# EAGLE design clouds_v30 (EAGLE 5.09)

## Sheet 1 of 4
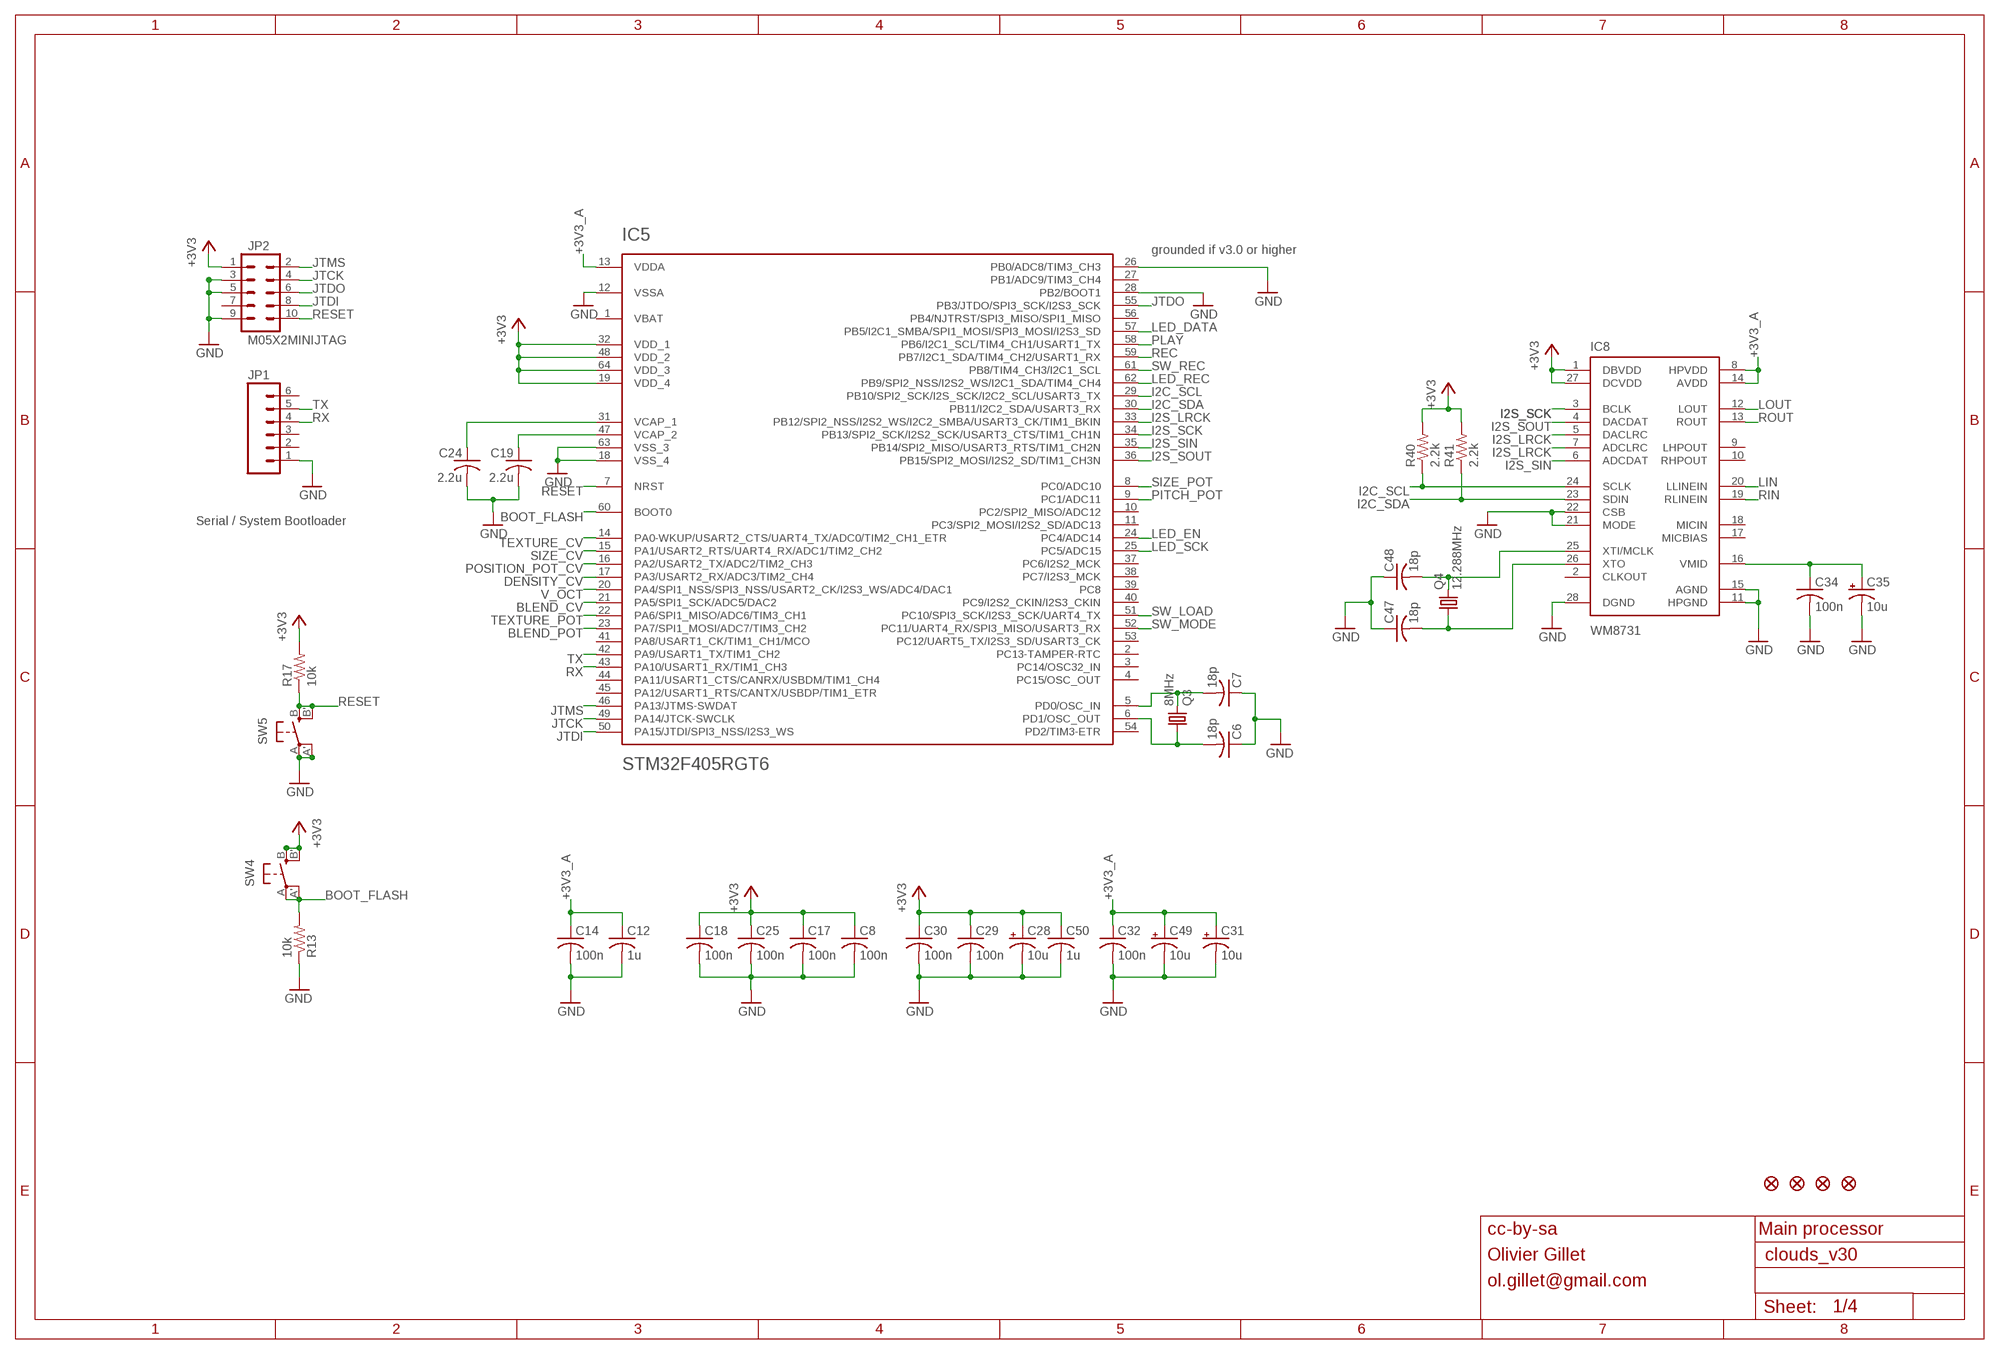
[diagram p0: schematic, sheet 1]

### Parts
C6  18p  C-USC0603  [C0603]
C7  18p  C-USC0603  [C0603]
C8  100n  C-USC0603  [C0603]
C12  1u  C-USC0603  [C0603]
C14  100n  C-USC0603  [C0603]
C17  100n  C-USC0603  [C0603]
C18  100n  C-USC0603  [C0603]
C19  2.2u  C-USC0805  [C0805]
C24  2.2u  C-USC0805  [C0805]
C25  100n  C-USC0603  [C0603]
C28  10u  CPOL-USA  [PANASONIC_A]
C29  100n  C-USC0603  [C0603]
C30  100n  C-USC0603  [C0603]
C31  10u  CPOL-USB  [PANASONIC_B]
C32  100n  C-USC0603  [C0603]
C34  100n  C-USC0603  [C0603]
C35  10u  CPOL-USB  [PANASONIC_B]
C47  18p  C-USC0603  [C0603]
C48  18p  C-USC0603  [C0603]
C49  10u  CPOL-USA  [PANASONIC_A]
C50  1u  C-USC0603  [C0603]
F1  FIDUCIAL1X2  [FIDUCIAL-1X2]
F2  FIDUCIAL1X2  [FIDUCIAL-1X2]
F3  FIDUCIAL1X2  [FIDUCIAL-1X2]
F4  FIDUCIAL1X2  [FIDUCIAL-1X2]
IC5  STM32F405RGT6  STM32F20X  [TQFP-10X10-64]
IC8  WM8731  [SSOP28]
JP1  M06SIP  [1X06]
JP2  M05X2MINIJTAG  [2X5-1.27]
Q3  8MHz  CRYSTALHC49UP  [HC49UP]
Q4  12.288MHz  CRYSTALHC49UP  [HC49UP]
R13  10k  R-US_R0603  [R0603]
R17  10k  R-US_R0603  [R0603]
R40  2.2k  R-US_R0603  [R0603]
R41  2.2k  R-US_R0603  [R0603]
SW4  EVQQ2  [EVQ-Q2]
SW5  EVQQ2  [EVQ-Q2]

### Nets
+3V3: C8.1 C17.1 C18.1 C25.1 C28.+ C29.1 C30.1 C50.1 IC5.19(VDD_4) IC5.32(VDD_1) IC5.48(VDD_2) IC5.64(VDD_3) IC8.1(DBVDD) IC8.27(DCVDD) JP2.1 R17.2 R40.2 R41.2 SW4.B'(S1) SW4.B(S) ; also sheet 3,4
+3V3_A: C12.1 C14.1 C31.+ C32.1 C49.+ IC5.13(VDDA) IC8.8(HPVDD) IC8.14(AVDD) ; also sheet 2,3,4
BLEND_CV: IC5.21(PA5/SPI1_SCK/ADC5/DAC2) ; also sheet 2
BLEND_POT: IC5.23(PA7/SPI1_MOSI/ADC7/TIM3_CH2) ; also sheet 3
BOOT_FLASH: IC5.60(BOOT0) R13.2 SW4.A'(P1) SW4.A(P)
DENSITY_CV: IC5.17(PA3/USART2_RX/ADC3/TIM2_CH4) ; also sheet 2
GND: C6.1 C7.1 C8.2 C12.2 C14.2 C17.2 C18.2 C19.2 C24.2 C25.2 C28.- C29.2 C30.2 C31.- C32.2 C34.2 C35.- C47.1 C48.1 C49.- C50.2 IC5.12(VSSA) IC5.18(VSS_4) IC5.26(PB0/ADC8/TIM3_CH3) IC5.28(PB2/BOOT1) IC5.63(VSS_3) IC8.11(HPGND) IC8.15(AGND) IC8.21(MODE) IC8.22(CSB) IC8.28(DGND) JP1.1 JP2.3 JP2.5 JP2.9 R13.1 SW5.A'(P1) SW5.A(P) ; also sheet 2,3,4
I2C_SCL: IC5.29(PB10/SPI2_SCK/I2S_SCK/I2C2_SCL/USART3_TX) IC8.24(SCLK) R40.1
I2C_SDA: IC5.30(PB11/I2C2_SDA/USART3_RX) IC8.23(SDIN) R41.1
I2S_LRCK: IC5.33(PB12/SPI2_NSS/I2S2_WS/I2C2_SMBA/USART3_CK/TIM1_BKIN) IC8.5(DACLRC) IC8.7(ADCLRC)
I2S_SCK: IC5.34(PB13/SPI2_SCK/I2S2_SCK/USART3_CTS/TIM1_CH1N) IC8.3(BCLK)
I2S_SIN: IC5.35(PB14/SPI2_MISO/USART3_RTS/TIM1_CH2N) IC8.6(ADCDAT)
I2S_SOUT: IC5.36(PB15/SPI2_MOSI/I2S2_SD/TIM1_CH3N) IC8.4(DACDAT)
JTCK: IC5.49(PA14/JTCK-SWCLK) JP2.4
JTDI: IC5.50(PA15/JTDI/SPI3_NSS/I2S3_WS) JP2.8
JTDO: IC5.55(PB3/JTDO/SPI3_SCK/I2S3_SCK) JP2.6
JTMS: IC5.46(PA13/JTMS-SWDAT) JP2.2
LED_DATA: IC5.57(PB5/I2C1_SMBA/SPI1_MOSI/SPI3_MOSI/I2S3_SD) ; also sheet 3
LED_EN: IC5.24(PC4/ADC14) ; also sheet 3
LED_REC: IC5.62(PB9/SPI2_NSS/I2S2_WS/I2C1_SDA/TIM4_CH4) ; also sheet 3
LED_SCK: IC5.25(PC5/ADC15) ; also sheet 3
LIN: IC8.20(LLINEIN) ; also sheet 2
LOUT: IC8.12(LOUT) ; also sheet 2
N$7: C7.2 IC5.5(PD0/OSC_IN) Q3.2
N$8: C6.2 IC5.6(PD1/OSC_OUT) Q3.1
N$13: C19.1 IC5.47(VCAP_2)
N$17: C34.1 C35.+ IC8.16(VMID)
N$19: C24.1 IC5.31(VCAP_1)
N$59: C47.2 IC8.26(XTO) Q4.1
N$60: C48.2 IC8.25(XTI/MCLK) Q4.2
PITCH_POT: IC5.9(PC1/ADC11) ; also sheet 3
PLAY: IC5.58(PB6/I2C1_SCL/TIM4_CH1/USART1_TX) ; also sheet 3
POSITION_POT_CV: IC5.16(PA2/USART2_TX/ADC2/TIM2_CH3) ; also sheet 2
REC: IC5.59(PB7/I2C1_SDA/TIM4_CH2/USART1_RX) ; also sheet 3
RESET: IC5.7(NRST) JP2.10 R17.1 SW5.B'(S1) SW5.B(S)
RIN: IC8.19(RLINEIN) ; also sheet 2
ROUT: IC8.13(ROUT) ; also sheet 2
RX: IC5.43(PA10/USART1_RX/TIM1_CH3) JP1.4
SIZE_CV: IC5.15(PA1/USART2_RTS/UART4_RX/ADC1/TIM2_CH2) ; also sheet 2
SIZE_POT: IC5.8(PC0/ADC10) ; also sheet 3
SW_LOAD: IC5.51(PC10/SPI3_SCK/I2S3_SCK/UART4_TX) ; also sheet 3
SW_MODE: IC5.52(PC11/UART4_RX/SPI3_MISO/USART3_RX) ; also sheet 3
SW_REC: IC5.61(PB8/TIM4_CH3/I2C1_SCL) ; also sheet 3
TEXTURE_CV: IC5.14(PA0-WKUP/USART2_CTS/UART4_TX/ADC0/TIM2_CH1_ETR) ; also sheet 2
TEXTURE_POT: IC5.22(PA6/SPI1_MISO/ADC6/TIM3_CH1) ; also sheet 3
TX: IC5.42(PA9/USART1_TX/TIM1_CH2) JP1.5
V_OCT: IC5.20(PA4/SPI1_NSS/SPI3_NSS/USART2_CK/I2S3_WS/ADC4/DAC1) ; also sheet 2
Unconnected: IC5.2(PC13-TAMPER-RTC) IC5.3(PC14/OSC32_IN) IC5.4(PC15/OSC_OUT) IC5.10(PC2/SPI2_MISO/ADC12) IC5.11(PC3/SPI2_MOSI/I2S2_SD/ADC13) IC5.27(PB1/ADC9/TIM3_CH4) IC5.37(PC6/I2S2_MCK) IC5.38(PC7/I2S3_MCK) IC5.39(PC8) IC5.40(PC9/I2S2_CKIN/I2S3_CKIN) IC5.41(PA8/USART1_CK/TIM1_CH1/MCO) IC5.44(PA11/USART1_CTS/CANRX/USBDM/TIM1_CH4) IC5.45(PA12/USART1_RTS/CANTX/USBDP/TIM1_ETR) IC5.53(PC12/UART5_TX/I2S3_SD/USART3_CK) IC5.54(PD2/TIM3-ETR) IC5.56(PB4/NJTRST/SPI3_MISO/SPI1_MISO) IC8.2(CLKOUT) IC8.9(LHPOUT) IC8.10(RHPOUT) IC8.17(MICBIAS) IC8.18(MICIN) JP1.2 JP1.3 JP1.6 JP2.7

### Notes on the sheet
- grounded if v3.0 or higher
- Serial / System Bootloader
- cc-by-sa | Main processor
- Olivier Gillet
- ol.gillet@gmail.com

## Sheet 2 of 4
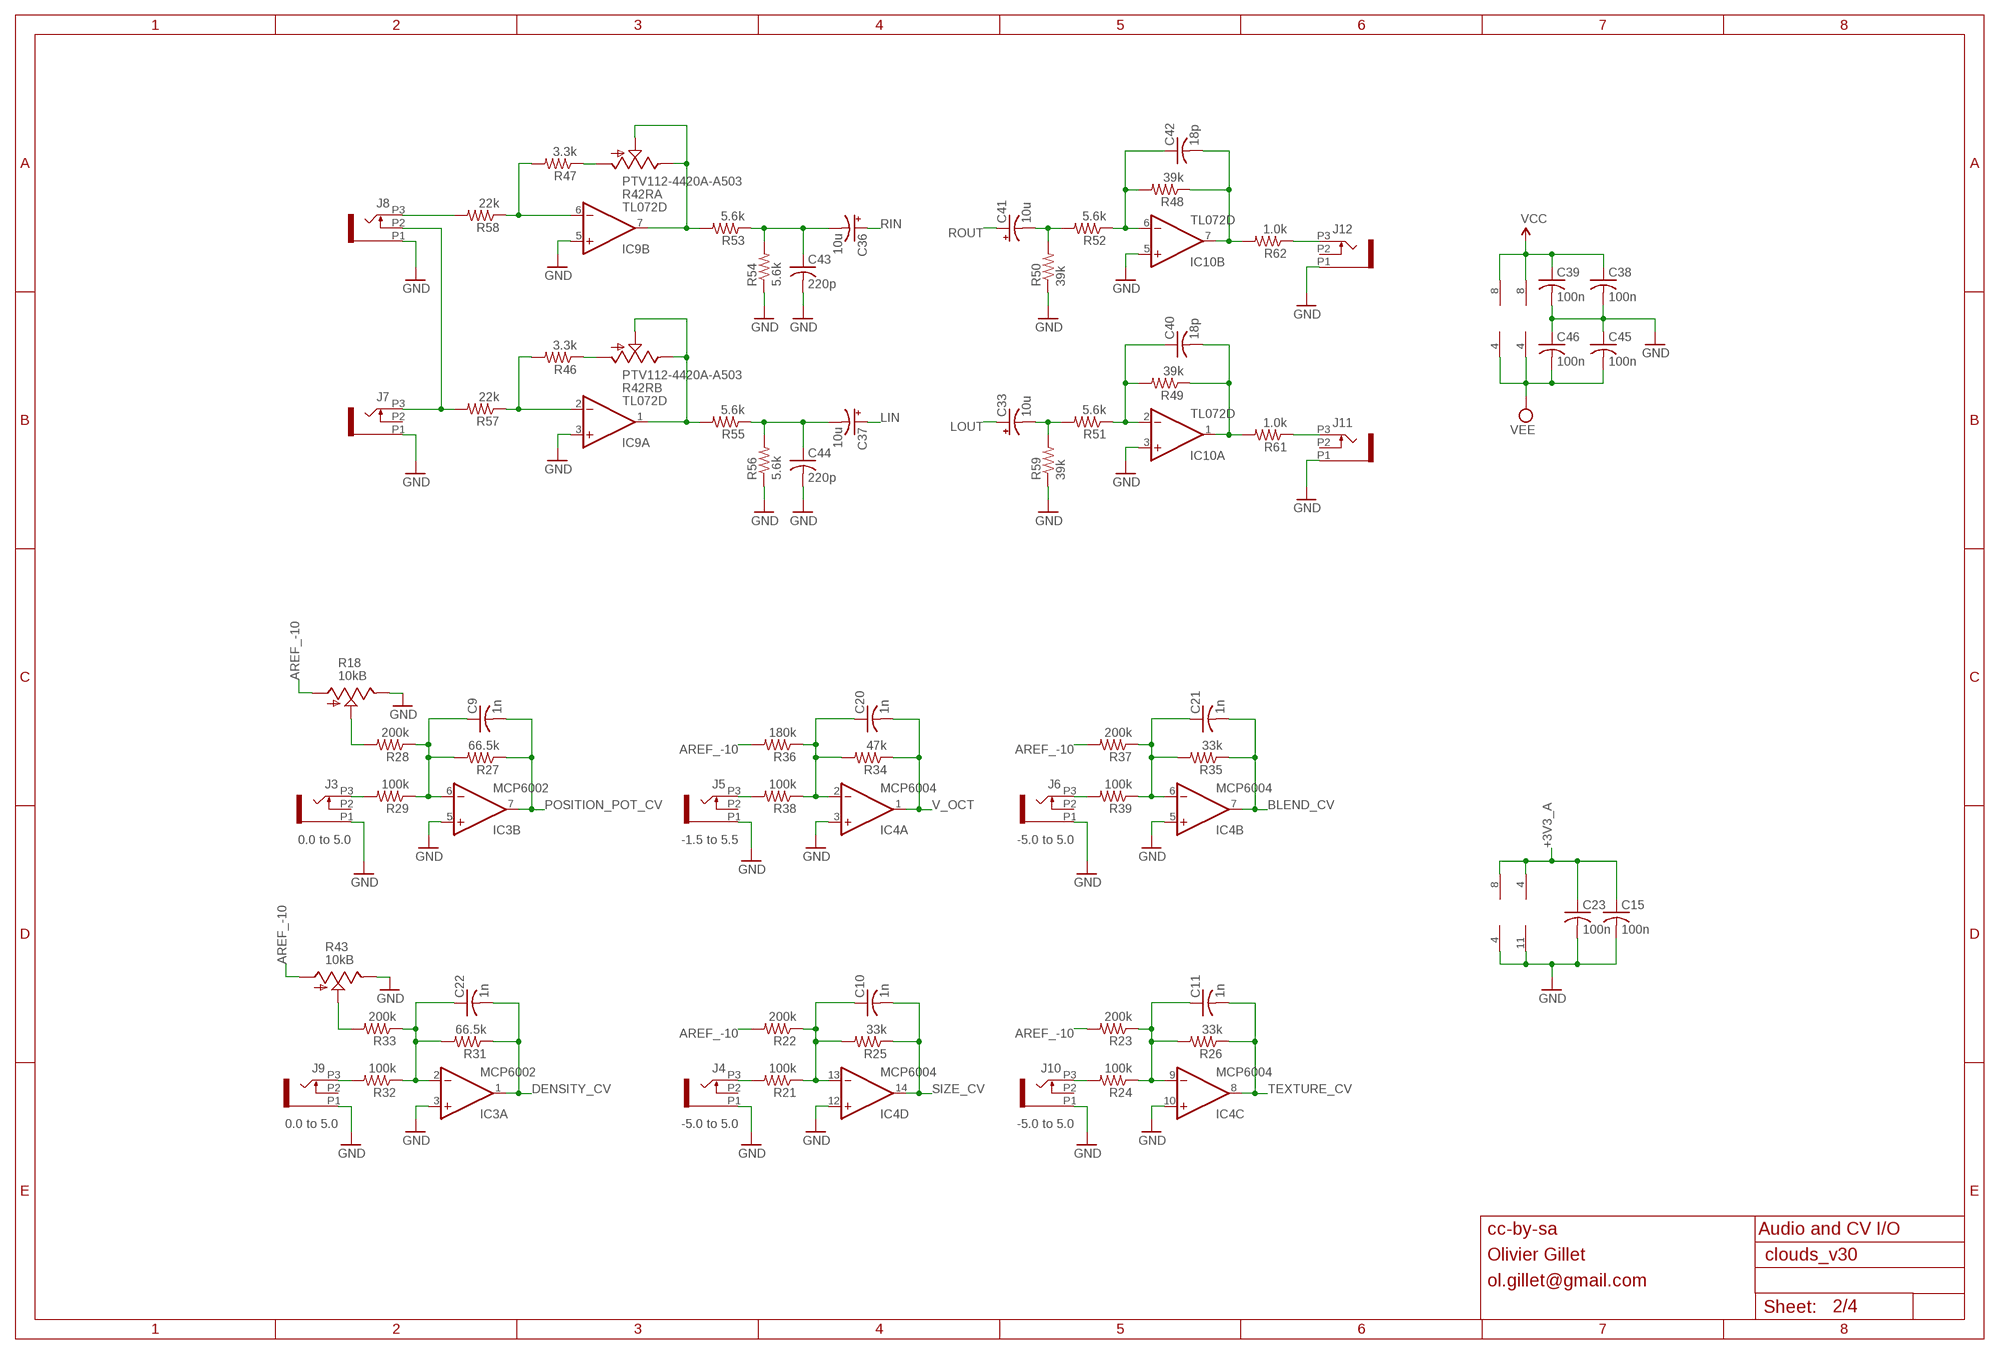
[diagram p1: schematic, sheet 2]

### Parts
C9  1n  C-USC0603  [C0603]
C10  1n  C-USC0603  [C0603]
C11  1n  C-USC0603  [C0603]
C15  100n  C-USC0603  [C0603]
C20  1n  C-USC0603  [C0603]
C21  1n  C-USC0603  [C0603]
C22  1n  C-USC0603  [C0603]
C23  100n  C-USC0603  [C0603]
C33  10u  CPOL-USB  [PANASONIC_B]
C36  10u  CPOL-USB  [PANASONIC_B]
C37  10u  CPOL-USB  [PANASONIC_B]
C38  100n  C-USC0603  [C0603]
C39  100n  C-USC0603  [C0603]
C40  18p  C-USC0603  [C0603]
C41  10u  CPOL-USB  [PANASONIC_B]
C42  18p  C-USC0603  [C0603]
C43  220p  C-USC0603  [C0603]
C44  220p  C-USC0603  [C0603]
C45  100n  C-USC0603  [C0603]
C46  100n  C-USC0603  [C0603]
IC3  MCP6002  TL072D  [SO08]
IC4  MCP6004  TL074D  [SO14]
IC9  TL072D  [SO08]
IC10  TL072D  [SO08]
J3  PJ301_THONKICONN6  [WQP_PJ_301M6]
J4  PJ301_THONKICONN6  [WQP_PJ_301M6]
J5  PJ301_THONKICONN6  [WQP_PJ_301M6]
J6  PJ301_THONKICONN6  [WQP_PJ_301M6]
J7  PJ301_THONKICONN6  [WQP_PJ_301M6]
J8  PJ301_THONKICONN6  [WQP_PJ_301M6]
J9  PJ301_THONKICONN6  [WQP_PJ_301M6]
J10  PJ301_THONKICONN6  [WQP_PJ_301M6]
J11  PJ301_THONKICONN6  [WQP_PJ_301M6]
J12  PJ301_THONKICONN6  [WQP_PJ_301M6]
R18  10kB  POT_USVERTICAL_PS  [ALPS_POT_VERTICAL_PS]
R21  100k  R-US_R0603  [R0603]
R22  200k  R-US_R0603  [R0603]
R23  200k  R-US_R0603  [R0603]
R24  100k  R-US_R0603  [R0603]
R25  33k  R-US_R0603  [R0603]
R26  33k  R-US_R0603  [R0603]
R27  66.5k  R-US_R0603  [R0603]
R28  200k  R-US_R0603  [R0603]
R29  100k  R-US_R0603  [R0603]
R31  66.5k  R-US_R0603  [R0603]
R32  100k  R-US_R0603  [R0603]
R33  200k  R-US_R0603  [R0603]
R34  47k  R-US_R0603  [R0603]
R35  33k  R-US_R0603  [R0603]
R36  180k  R-US_R0603  [R0603]
R37  200k  R-US_R0603  [R0603]
R38  100k  R-US_R0603  [R0603]
R39  100k  R-US_R0603  [R0603]
R42  PTV112-4420A-A503  POT_US_DUAL_GANG  [BOURNS_PTV112]
R43  10kB  POT_USVERTICAL_PS  [ALPS_POT_VERTICAL_PS]
R46  3.3k  R-US_R0603  [R0603]
R47  3.3k  R-US_R0603  [R0603]
R48  39k  R-US_R0603  [R0603]
R49  39k  R-US_R0603  [R0603]
R50  39k  R-US_R0603  [R0603]
R51  5.6k  R-US_R0603  [R0603]
R52  5.6k  R-US_R0603  [R0603]
R53  5.6k  R-US_R0603  [R0603]
R54  5.6k  R-US_R0603  [R0603]
R55  5.6k  R-US_R0603  [R0603]
R56  5.6k  R-US_R0603  [R0603]
R57  22k  R-US_R0603  [R0603]
R58  22k  R-US_R0603  [R0603]
R59  39k  R-US_R0603  [R0603]
R61  1.0k  R-US_R0603  [R0603]
R62  1.0k  R-US_R0603  [R0603]

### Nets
+3V3_A: C15.1 C23.1 IC3.8(P:V+) IC4.4(P:V+) ; also sheet 1,3,4
AREF_-10: R18.P$3(A) R22.2 R23.2 R36.2 R37.2 R43.P$3(A) ; also sheet 4
BLEND_CV: C21.2 IC4.7(B:OUT) R35.1 ; also sheet 1
DENSITY_CV: C22.2 IC3.1(A:OUT) R31.1 ; also sheet 1
GND: C15.2 C23.2 C38.2 C39.2 C43.2 C44.2 C45.1 C46.1 IC3.3(A:+IN) IC3.4(P:V-) IC3.5(B:+IN) IC4.3(A:+IN) IC4.5(B:+IN) IC4.10(C:+IN) IC4.11(P:V-) IC4.12(D:+IN) IC9.3(A:+IN) IC9.5(B:+IN) IC10.3(A:+IN) IC10.5(B:+IN) J3.P1 J4.P1 J5.P1 J6.P1 J7.P1 J8.P1 J9.P1 J10.P1 J11.P1 J12.P1 R18.P$1(E) R43.P$1(E) R50.1 R54.1 R56.1 R59.1 ; also sheet 1,3,4
LIN: C37.+ ; also sheet 1
LOUT: C33.+ ; also sheet 1
LOUT_JACK: J11.P3 R61.1
N$1: J4.P3 R21.2
N$2: C10.1 IC4.13(D:-IN) R21.1 R22.1 R25.2
N$4: J10.P3 R24.2
N$5: C11.1 IC4.9(C:-IN) R23.1 R24.1 R26.2
N$6: J6.P3 R39.2
N$10: J5.P3 R38.2
N$11: C20.1 IC4.2(A:-IN) R34.2 R36.1 R38.1
N$14: J9.P3 R32.2
N$15: C21.1 IC4.6(B:-IN) R35.2 R37.1 R39.1
N$18: C37.- C44.1 R55.1 R56.2
N$20: J8.P3 R58.2
N$21: J7.P3 J8.P2 R57.2
N$22: C36.- C43.1 R53.1 R54.2
N$23: C41.- R50.2 R52.2
N$24: C22.1 IC3.2(A:-IN) R31.2 R32.1 R33.1
N$25: C42.1 IC10.6(B:-IN) R48.2 R52.1
N$26: R33.2 R43.P$2(S)
N$27: J3.P3 R29.2
N$28: C42.2 IC10.7(B:OUT) R48.1 R62.2
N$30: C9.1 IC3.6(B:-IN) R27.2 R28.1 R29.1
N$31: C33.- R51.2 R59.2
N$32: C40.1 IC10.2(A:-IN) R49.2 R51.1
N$33: C40.2 IC10.1(A:OUT) R49.1 R61.2
N$35: R18.P$2(S) R28.2
N$42: IC9.7(B:OUT) R42.2P(RA:S) R42.3P(RA:E) R53.2
N$51: IC9.1(A:OUT) R42.2(RB:S) R42.3(RB:E) R55.2
N$52: R42.1P(RA:A) R47.1
N$53: R42.1(RB:A) R46.1
N$54: IC9.6(B:-IN) R47.2 R58.1
N$58: IC9.2(A:-IN) R46.2 R57.1
POSITION_POT_CV: C9.2 IC3.7(B:OUT) R27.1 ; also sheet 1
RIN: C36.+ ; also sheet 1
ROUT: C41.+ ; also sheet 1
ROUT_JACK: J12.P3 R62.1
SIZE_CV: C10.2 IC4.14(D:OUT) R25.1 ; also sheet 1
TEXTURE_CV: C11.2 IC4.8(C:OUT) R26.1 ; also sheet 1
V_OCT: C20.2 IC4.1(A:OUT) R34.1 ; also sheet 1
VCC: C38.1 C39.1 IC9.8(P:V+) IC10.8(P:V+) ; also sheet 4
VEE: C45.2 C46.2 IC9.4(P:V-) IC10.4(P:V-) ; also sheet 4
Unconnected: J3.P2 J4.P2 J5.P2 J6.P2 J7.P2 J9.P2 J10.P2 J11.P2 J12.P2

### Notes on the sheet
- 0.0 to 5.0 | -1.5 to 5.5 | -5.0 to 5.0
- 0.0 to 5.0 | -5.0 to 5.0 | -5.0 to 5.0
- cc-by-sa | Audio and CV I/O
- Olivier Gillet
- ol.gillet@gmail.com

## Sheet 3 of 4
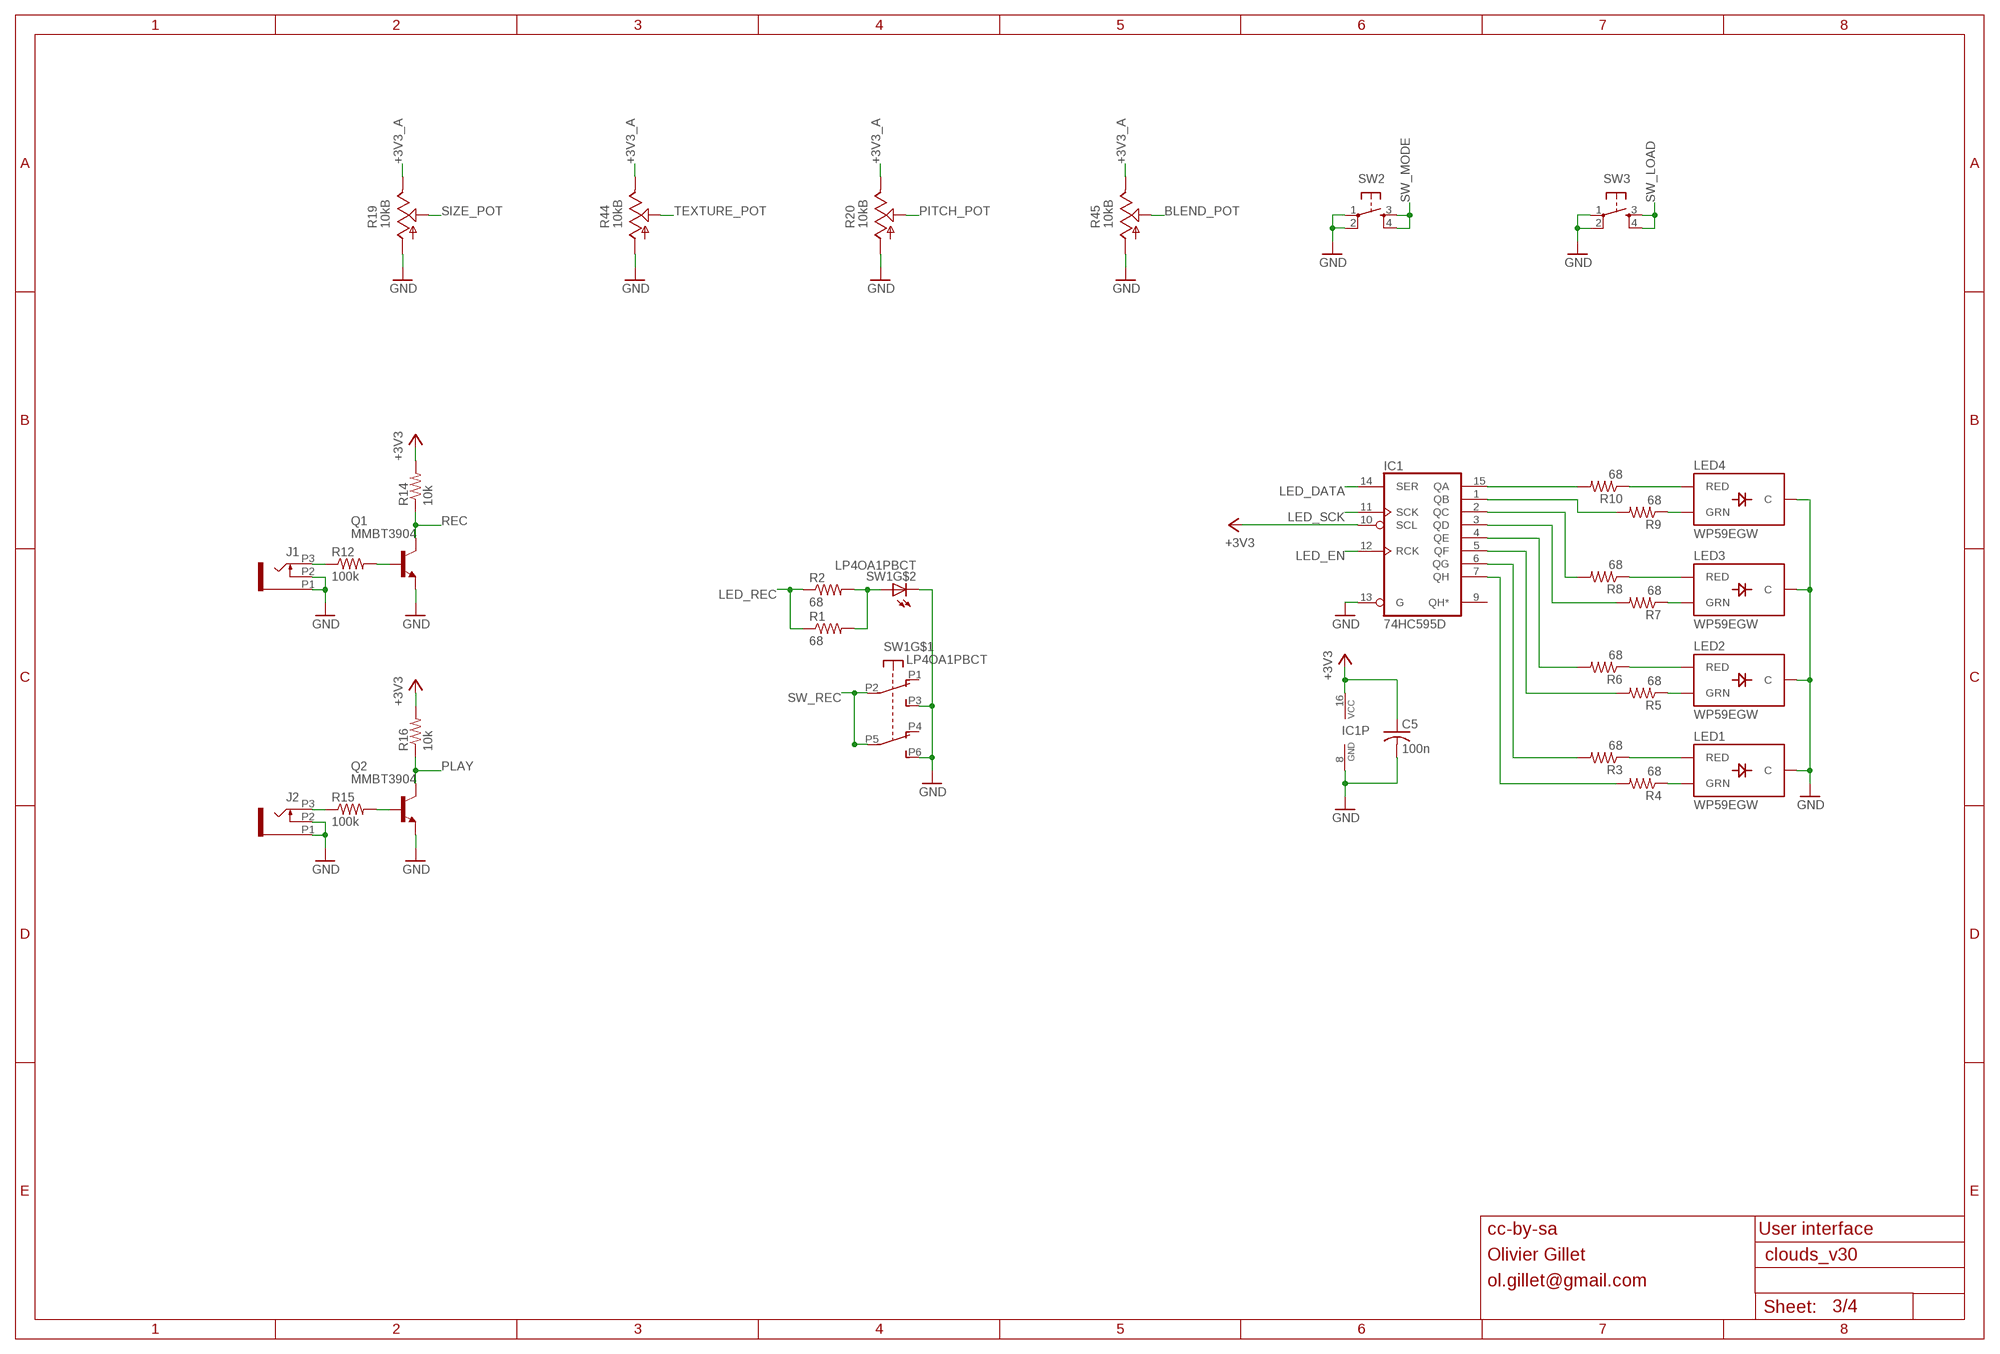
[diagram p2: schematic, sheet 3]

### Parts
C5  100n  C-USC0603  [C0603]
IC1  74HC595D  [SO16]
J1  PJ301_THONKICONN6  [WQP_PJ_301M6]
J2  PJ301_THONKICONN6  [WQP_PJ_301M6]
LED1  WP59EGW  LED-BICOLOR-THROUGHHOLE5MM  [LED-BICOLOR-THROUGHHOLE-5MM]
LED2  WP59EGW  LED-BICOLOR-THROUGHHOLE5MM  [LED-BICOLOR-THROUGHHOLE-5MM]
LED3  WP59EGW  LED-BICOLOR-THROUGHHOLE5MM  [LED-BICOLOR-THROUGHHOLE-5MM]
LED4  WP59EGW  LED-BICOLOR-THROUGHHOLE5MM  [LED-BICOLOR-THROUGHHOLE-5MM]
Q1  MMBT3904  MMBT3904LT1-NPN-SOT23-BEC  [SOT23-BEC]
Q2  MMBT3904  MMBT3904LT1-NPN-SOT23-BEC  [SOT23-BEC]
R1  68  R-US_R0603  [R0603]
R2  68  R-US_R0603  [R0603]
R3  68  R-US_R0603  [R0603]
R4  68  R-US_R0603  [R0603]
R5  68  R-US_R0603  [R0603]
R6  68  R-US_R0603  [R0603]
R7  68  R-US_R0603  [R0603]
R8  68  R-US_R0603  [R0603]
R9  68  R-US_R0603  [R0603]
R10  68  R-US_R0603  [R0603]
R12  100k  R-US_R0603  [R0603]
R14  10k  R-US_R0603  [R0603]
R15  100k  R-US_R0603  [R0603]
R16  10k  R-US_R0603  [R0603]
R19  10kB  POT_USVERTICAL_PS  [ALPS_POT_VERTICAL_PS]
R20  10kB  POT_USVERTICAL_PS  [ALPS_POT_VERTICAL_PS]
R44  10kB  POT_USVERTICAL_PS  [ALPS_POT_VERTICAL_PS]
R45  10kB  POT_USVERTICAL_PS  [ALPS_POT_VERTICAL_PS]
SW1  LP4OA1PBCT  [LP4OA1PBCT]
SW2  TAC_SWITCHPTH  [TACTILE-PTH]
SW3  TAC_SWITCHPTH  [TACTILE-PTH]

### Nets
+3V3: C5.1 IC1.10(SCL) IC1.16(VCC) R14.2 R16.2 ; also sheet 1,4
+3V3_A: R19.P$1(E) R20.P$1(E) R44.P$1(E) R45.P$1(E) ; also sheet 1,2,4
BLEND_POT: R45.P$2(S) ; also sheet 1
GND: C5.2 IC1.8(GND) IC1.13(G) J1.P1 J1.P2 J2.P1 J2.P2 LED1.2(C) LED2.2(C) LED3.2(C) LED4.2(C) Q1.E Q2.E R19.P$3(A) R20.P$3(A) R44.P$3(A) R45.P$3(A) SW1.L2 SW1.P3(A3) SW1.P6(B3) SW2.1 SW2.2 SW3.1 SW3.2 ; also sheet 1,2,4
LED_DATA: IC1.14(SER) ; also sheet 1
LED_EN: IC1.12(RCK) ; also sheet 1
LED_REC: R1.1 R2.1 ; also sheet 1
LED_SCK: IC1.11(SCK) ; also sheet 1
N$9: LED4.3(GRN) R9.1
N$12: LED4.1(RED) R10.1
N$16: LED3.1(RED) R8.1
N$29: LED3.3(GRN) R7.1
N$34: LED2.1(RED) R6.1
N$36: J2.P3 R15.1
N$37: Q2.B R15.2
N$38: R1.2 R2.2 SW1.L1
N$39: LED2.3(GRN) R5.1
N$40: LED1.1(RED) R3.1
N$41: LED1.3(GRN) R4.1
N$43: IC1.15(QA) R10.2
N$44: IC1.1(QB) R9.2
N$45: IC1.2(QC) R8.2
N$46: IC1.3(QD) R7.2
N$47: IC1.4(QE) R6.2
N$48: IC1.5(QF) R5.2
N$49: IC1.6(QG) R3.2
N$50: IC1.7(QH) R4.2
N$57: J1.P3 R12.1
N$66: Q1.B R12.2
PITCH_POT: R20.P$2(S) ; also sheet 1
PLAY: Q2.C R16.1 ; also sheet 1
REC: Q1.C R14.1 ; also sheet 1
SIZE_POT: R19.P$2(S) ; also sheet 1
SW_LOAD: SW3.3 SW3.4 ; also sheet 1
SW_MODE: SW2.3 SW2.4 ; also sheet 1
SW_REC: SW1.P2(A2) SW1.P5(B2) ; also sheet 1
TEXTURE_POT: R44.P$2(S) ; also sheet 1
Unconnected: IC1.9(QH*) SW1.P1(A1) SW1.P4(B1)

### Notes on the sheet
- cc-by-sa | User interface
- Olivier Gillet
- ol.gillet@gmail.com

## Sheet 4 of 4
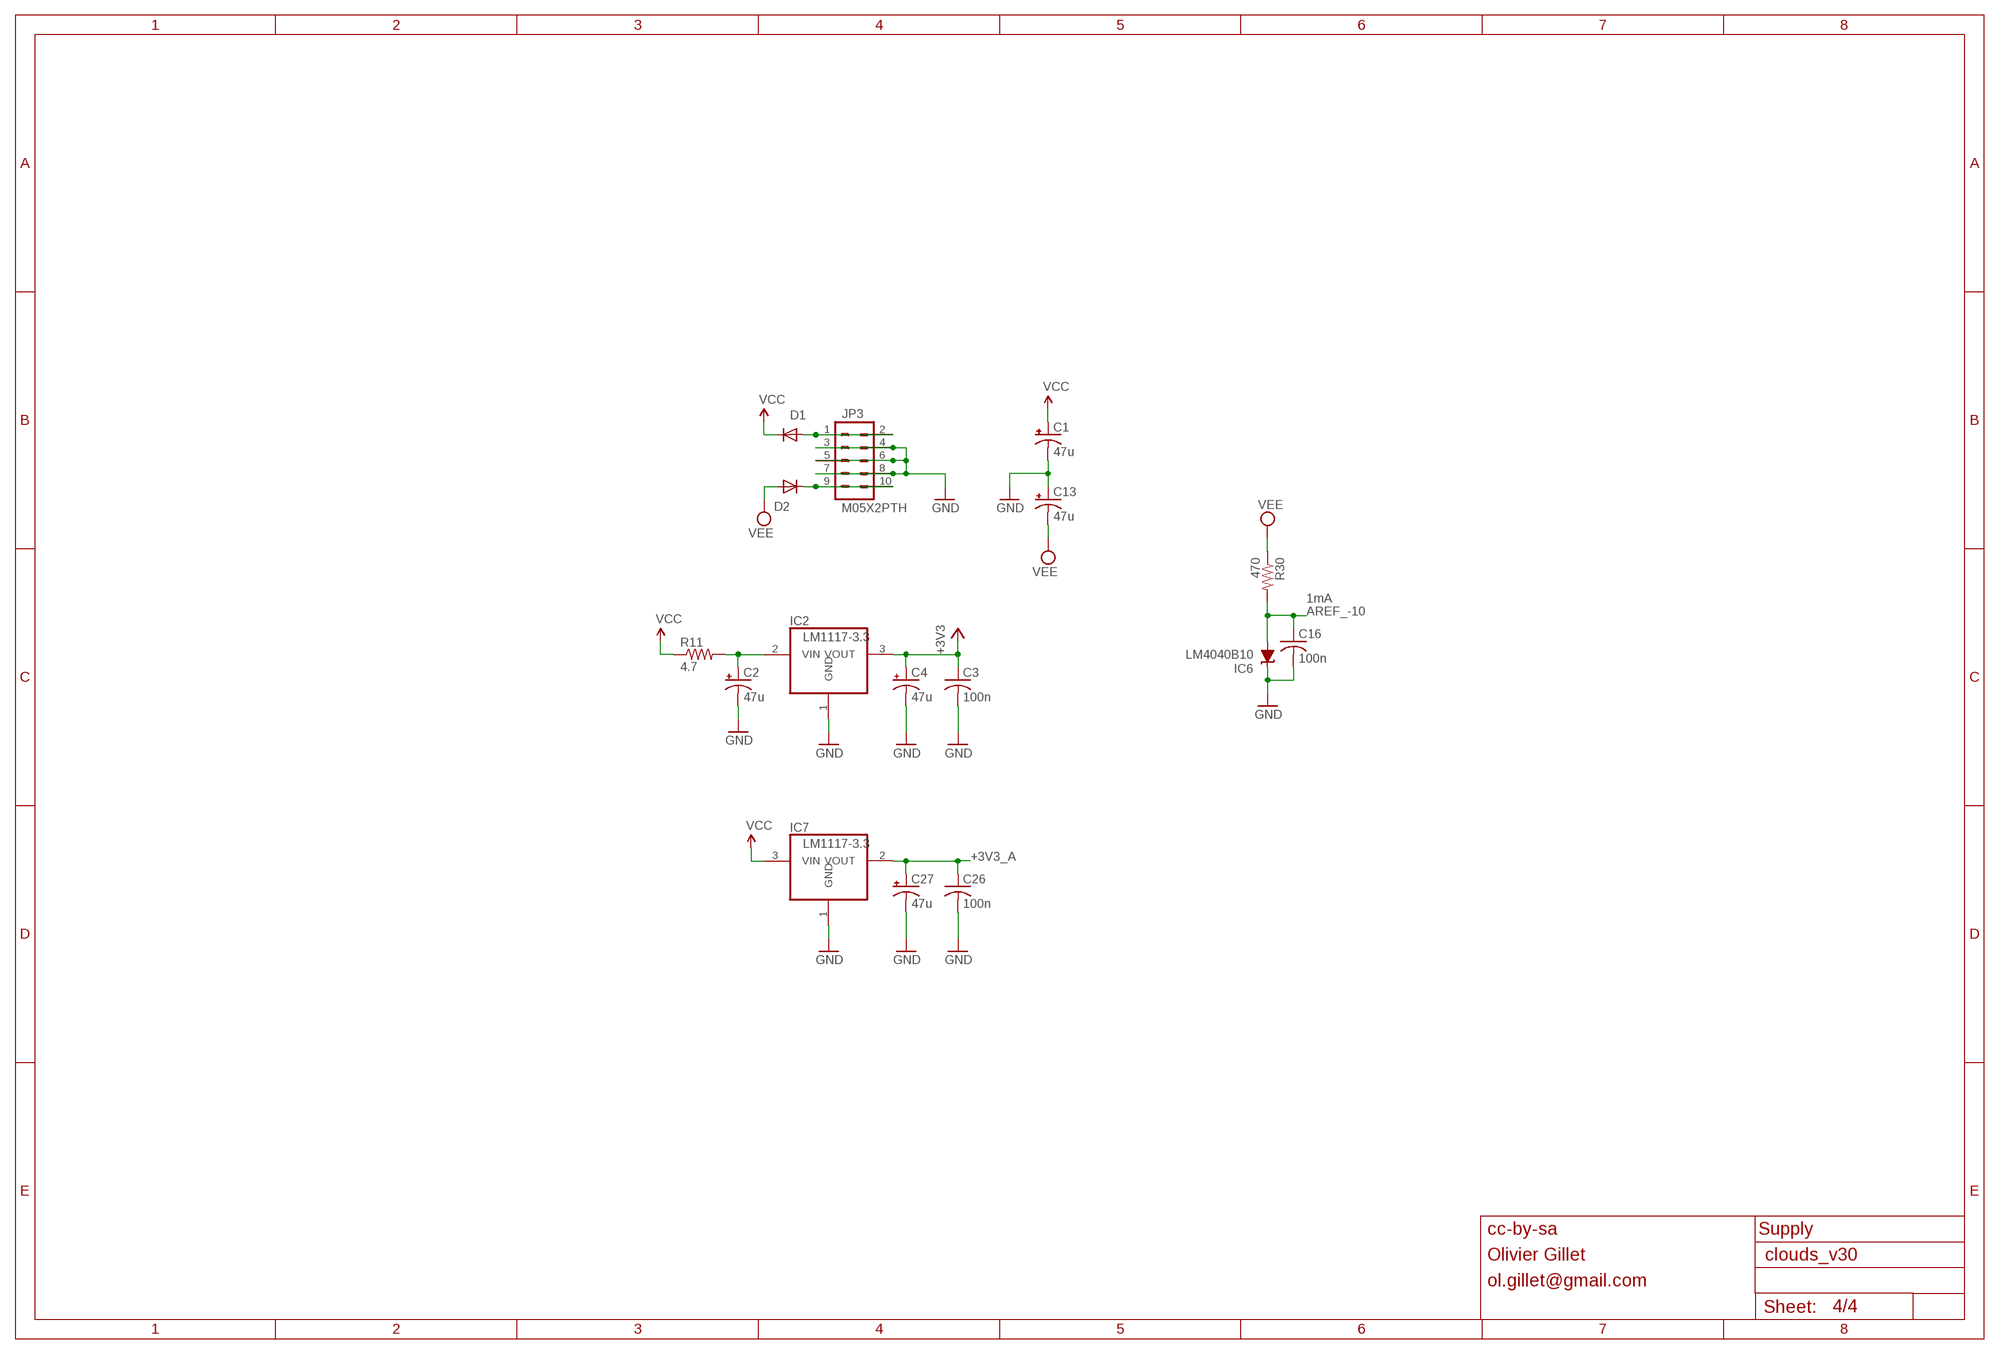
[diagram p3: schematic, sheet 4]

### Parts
C1  47u  CPOL-USD  [PANASONIC_D]
C2  47u  CPOL-USD  [PANASONIC_D]
C3  100n  C-USC0603  [C0603]
C4  47u  CPOL-USD  [PANASONIC_D]
C13  47u  CPOL-USD  [PANASONIC_D]
C16  100n  C-USC0603  [C0603]
C26  100n  C-USC0603  [C0603]
C27  47u  CPOL-USD  [PANASONIC_D]
D1  1N5819HW  DIODE-SOD123  [SOD123]
D2  1N5819HW  DIODE-SOD123  [SOD123]
IC2  LM1117-3.3  REG1117T  [TO252]
IC6  LM4040B10  LM4041B12DBZ  [DBZ_R-PDSO-G3]
IC7  LM1117-3.3  REG1117  [SOT223]
JP3  M05X2PTH  [AVR_ICSP]
R11  4.7  R-US_R1206  [R1206]
R30  470  R-US_R0603  [R0603]

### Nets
+3V3: C3.1 C4.+ IC2.3(VOUT) ; also sheet 1,3
+3V3_A: C26.1 C27.+ IC7.2(VOUT) ; also sheet 1,2,3
AREF_-10: C16.1 IC6.2(A) R30.2 ; also sheet 2
GND: C1.- C2.- C3.2 C4.- C13.+ C16.2 C26.2 C27.- IC2.1(GND) IC6.1(C) IC7.1(GND) JP3.3 JP3.4 JP3.5 JP3.6 JP3.7 JP3.8 ; also sheet 1,2,3
N$55: C2.+ IC2.2(VIN) R11.2
N$56: D1.A JP3.1 JP3.2
N$64: D2.C JP3.9 JP3.10
VCC: C1.+ D1.C IC7.3(VIN) R11.1 ; also sheet 2
VEE: C13.- D2.A R30.1 ; also sheet 2

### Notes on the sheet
- 1mA
- cc-by-sa | Supply
- Olivier Gillet
- ol.gillet@gmail.com

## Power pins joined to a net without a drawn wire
VBAT: IC5.1(VBAT)

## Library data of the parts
C1 C2 C4 C13 C27 C28 C31 C33 C35-C37 C41 C49 = rcl:CPOL-US: POLARIZED CAPACITOR, American symbol
C3 C5-C12 C14-C26 C29 C30 C32 C34 C38-C40 C42-C48 C50 = rcl:C-US: CAPACITOR, American symbol
D1 D2 = diode:DIODE-: DIODE
F1-F4 = SparkFun:FIDUCIAL: Fiducial Alignment Points
IC1 = 74xx-eu:74*595: 8-bit SHIFT REGISTER, output latch
IC2 IC7 = og-vreg:REG1117: 800mA and 1A Low Dropout (LDO) Positive Regulator 1.8V, 2.5V, 2.85V, 3.3V, 5V, and Adj
IC3 = gm-ics:TL072: OP AMP
IC4 = gm-ics:TL074: OP AMP
IC5 = og-stm32f2:STM32F20X
IC6 = texas:LM4041: PRECISION MICROPOWER SHUNT VOLTAGE REFERENCE
IC8 = og-dac:WM8731
IC9 IC10 = og-linear:TL072: OP AMP
J1-J12 = og-pj301:PJ301_THONKICONN
JP1 = SparkFun:M06: Header 6 Standard 6-pin 0.1" header. Use with straight break away headers (SKU : PRT-00116), right angle break away headers (PRT-00553), swiss pins (PRT-00743), machine pins (PRT-00117), and female headers (PRT-00115). Molex polarized connector foot print use with SKU : PRT-08094 with associated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
JP2 JP3 = og-header:M05X2: Header 5x2 Standard 10-pin dual row 0.1" header. Commonly used with AVR-ISP. Use with Spark Fun Electronics SKU: PRT-00778
LED1-LED4 = og-leds:LED-BICOLOR-THROUGHHOLE
Q1 Q2 = transistor:*-NPN-: NPN Transistror BF959 corrected 2008.03.06
Q3 Q4 = crystal:CRYSTAL: CRYSTAL
R1-R17 R21-R41 R46-R59 R61 R62 = rcl:R-US_: RESISTOR, American symbol
R18-R20 R43-R45 = og-pots:POT_US
R42 = og-pots:POT_US_DUAL_GANG
SW1 = og-switch:LP4OA1PBCT
SW2 SW3 = SparkFun:TAC_SWITCH: Momentary Switch Button commonly used for reset or general input. Spark Fun Electronics SKU : COM-00097
SW4 SW5 = adafruit:EVQQ2: SMT 6mm switch, EVQQ2 series http://www.ladyada.net/library/eagle

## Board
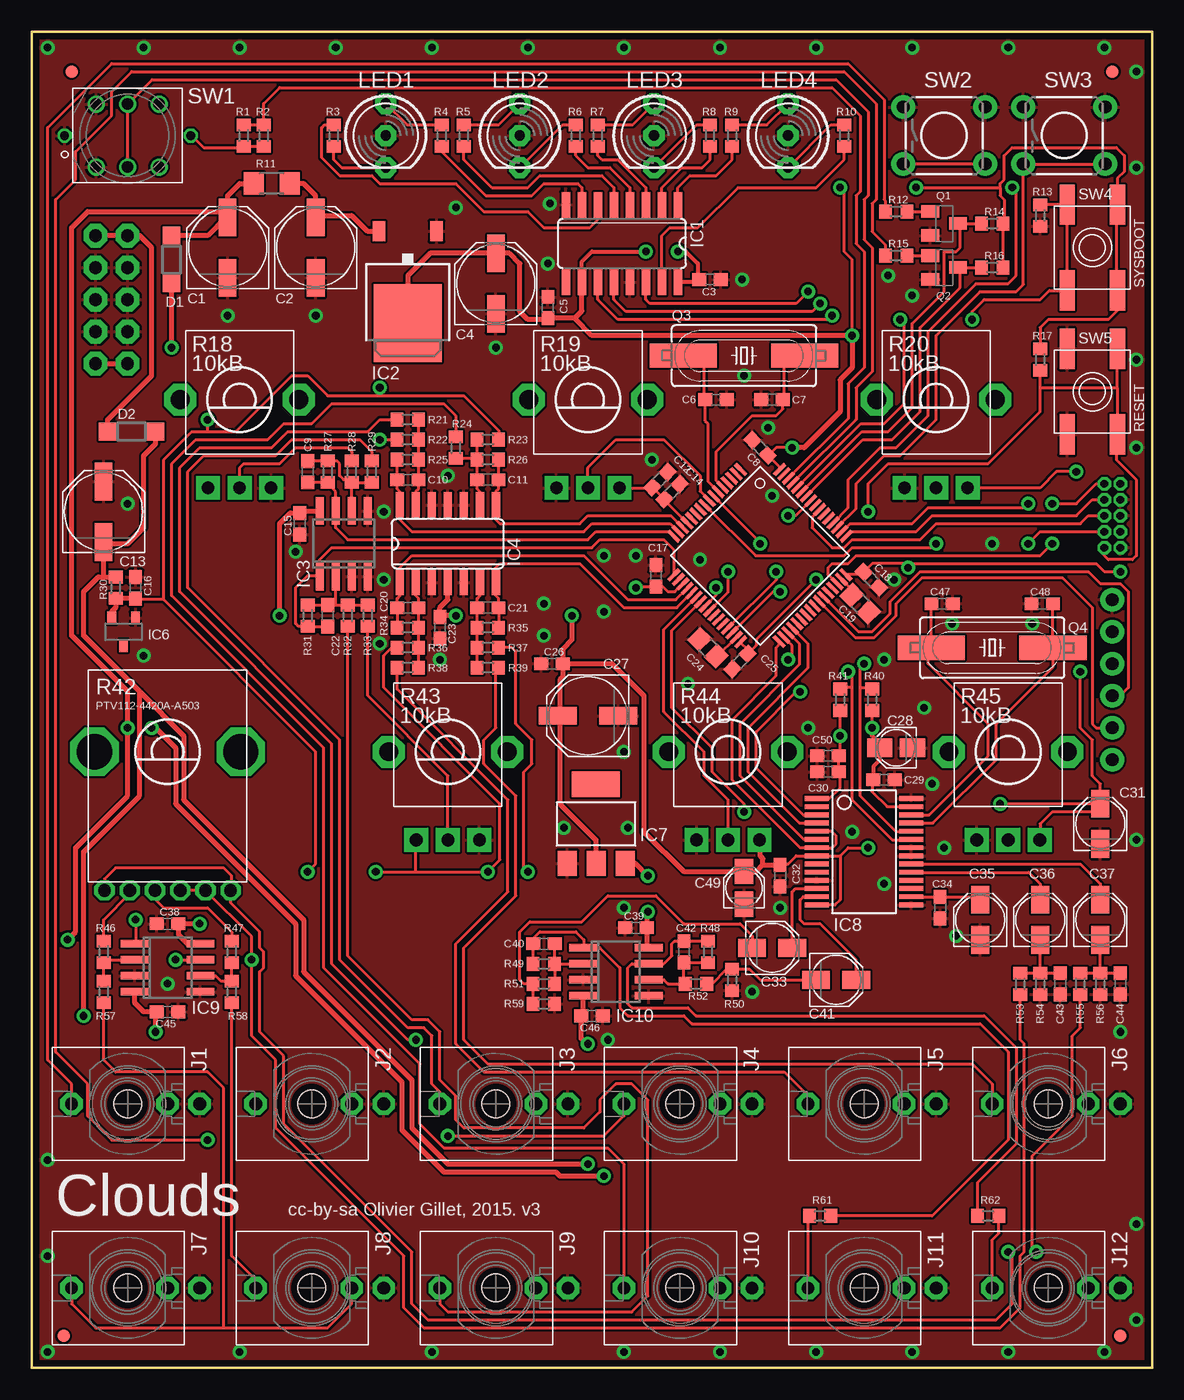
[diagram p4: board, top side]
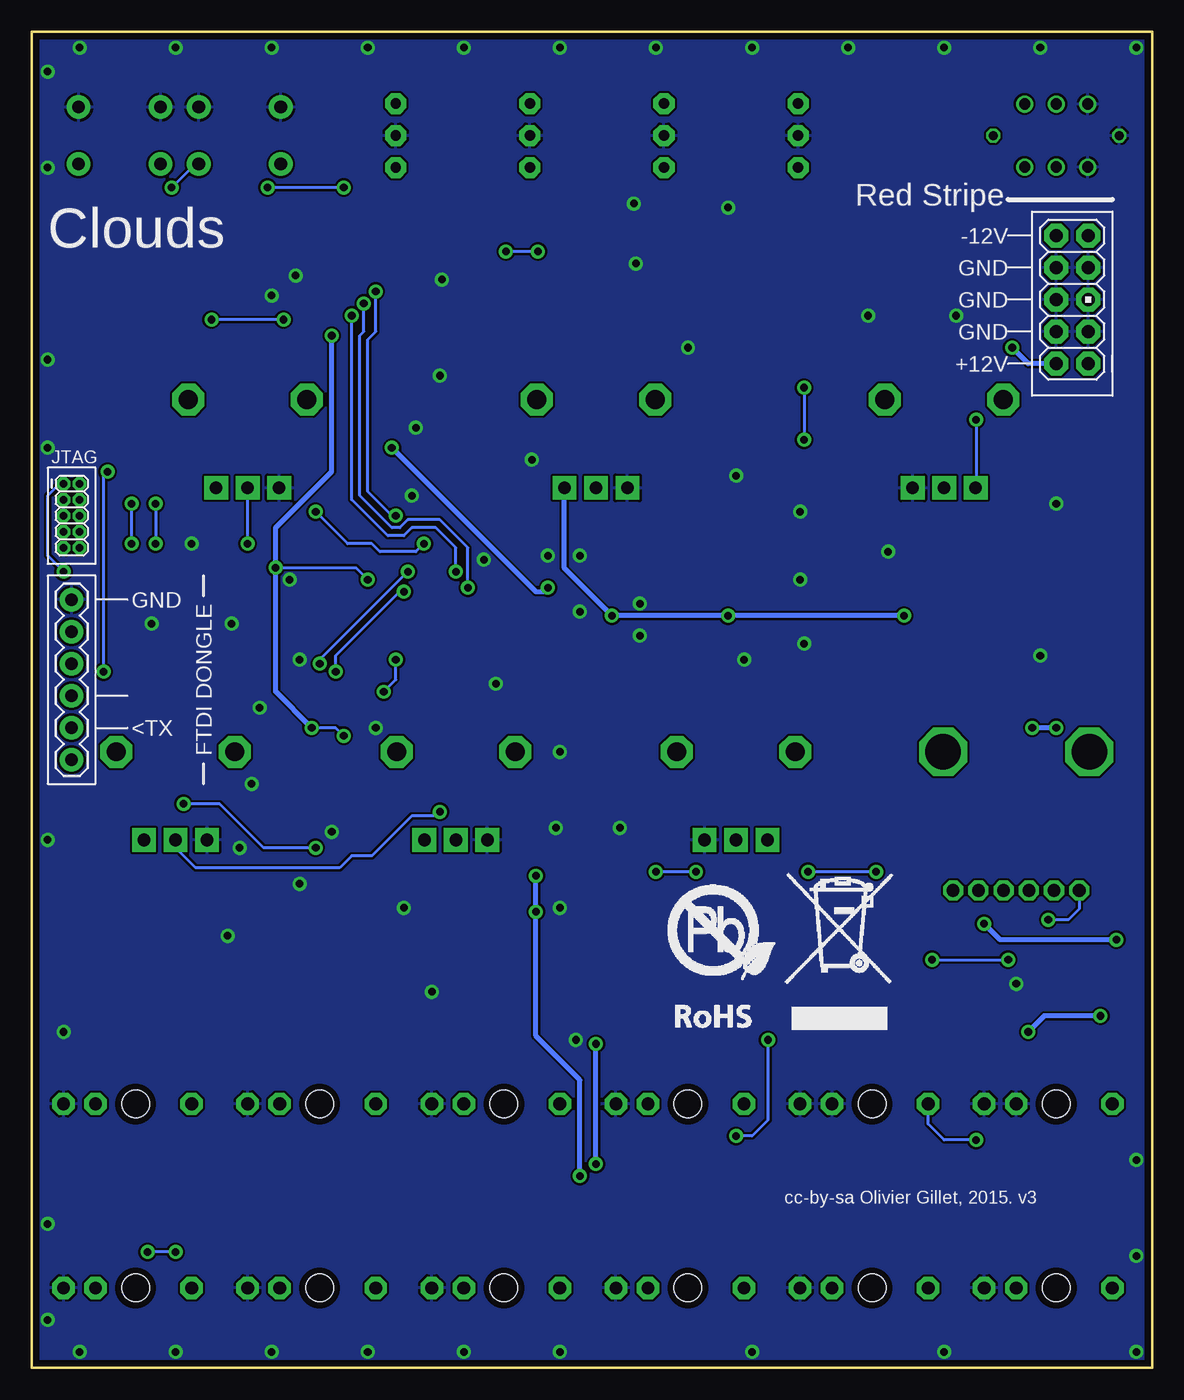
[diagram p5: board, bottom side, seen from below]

Size 88.9 x 106.05 mm. Coordinates in mm from the lower left corner, seen from the top.
Outline: 0,0 88.9,0 88.9,106.05 0,106.05 0,0
Copper layers (1*16): Top 0.035mm / dielectric 1.5mm / Bottom 0.035mm
Design rules "PCBCart-Standard-Fine": minimum track width 8mil, minimum drill 0.4mm, track to track 7mil, track to pad 7mil, pad to pad 7mil, via to via 7mil, smd to smd 7mil, copper to edge 20mil, drill to drill 8mil, minimum pad ring 8mil, minimum via ring 10mil, stop-mask expansion 3mil, vias tented up to drill 25mil, thermal gap 8mil

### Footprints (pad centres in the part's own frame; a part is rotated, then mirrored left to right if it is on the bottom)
PANASONIC_D = smd 3 x 1.4: + 2.4,0; - -2.4,0
C0603 = smd 1.1 x 1: 1 -0.85,0; 2 0.85,0
C0805 = smd 1.3 x 1.5: 1 -0.95,0; 2 0.95,0
PANASONIC_A = smd 2 x 1.5: + 1.3,0; - -1.3,0
PANASONIC_B = smd 2.2 x 1.4: + 1.6,0; - -1.6,0
SOD123 = smd 1.4 x 1.4: A 1.9,0; C -1.9,0
FIDUCIAL-1X2 = smd 1 x 1: 1 0,0
SO16 = smd 0.66 x 2.032: 1 -4.445,-3.073; 2 -3.175,-3.073; 3 -1.905,-3.073; 4 -0.635,-3.073; 5 0.635,-3.073; 6 1.905,-3.073; 7 3.175,-3.073; 8 4.445,-3.073; 9 4.445,3.073; 10 3.175,3.073; 11 1.905,3.073; 12 0.635,3.073; 13 -0.635,3.073; 14 -1.905,3.073; 15 -3.175,3.073; 16 -4.445,3.073
TO252 = smd 1 x 1.6: 1 -2.28,-4.8; 2 2.28,-4.8 | smd 5.4 x 6.2: 3 0,2.5
SO08 = smd 0.6 x 2.2: 1 -1.905,-2.6; 2 -0.635,-2.6; 3 0.635,-2.6; 4 1.905,-2.6; 5 1.905,2.6; 6 0.635,2.6; 7 -0.635,2.6; 8 -1.905,2.6
SO14 = smd 0.66 x 2.032: 1 -3.81,-3.073; 2 -2.54,-3.073; 3 -1.27,-3.073; 4 0,-3.073; 5 1.27,-3.073; 6 2.54,-3.073; 7 3.81,-3.073; 8 3.81,3.073; 9 2.54,3.073; 10 1.27,3.073; 11 0,3.073; 12 -1.27,3.073; 13 -2.54,3.073; 14 -3.81,3.073
TQFP-10X10-64 = smd 1.2 x 0.3: 1 -5.936,3.75; 2 -5.936,3.25; 3 -5.936,2.75; 4 -5.936,2.25; 5 -5.936,1.75; 6 -5.936,1.25; 7 -5.936,0.75; 8 -5.936,0.25; 9 -5.936,-0.25; 10 -5.936,-0.75; 11 -5.936,-1.25; 12 -5.936,-1.75; 13 -5.936,-2.25; 14 -5.936,-2.75; 15 -5.936,-3.25; 16 -5.936,-3.75; 33 5.886,-3.75; 34 5.886,-3.25; 35 5.886,-2.75; 36 5.886,-2.25; 37 5.886,-1.75; 38 5.886,-1.25; 39 5.886,-0.75; 40 5.886,-0.25; 41 5.886,0.25; 42 5.886,0.75; 43 5.886,1.25; 44 5.886,1.75; 45 5.886,2.25; 46 5.886,2.75; 47 5.886,3.25; 48 5.886,3.75 | smd 0.3 x 1.2: 17 -3.75,-5.911; 18 -3.25,-5.911; 19 -2.75,-5.911; 20 -2.25,-5.911; 21 -1.75,-5.911; 22 -1.25,-5.911; 23 -0.75,-5.911; 24 -0.25,-5.911; 25 0.25,-5.911; 26 0.75,-5.911; 27 1.25,-5.911; 28 1.75,-5.911; 29 2.25,-5.911; 30 2.75,-5.911; 31 3.25,-5.911; 32 3.75,-5.911; 49 3.75,5.936; 50 3.25,5.936; 51 2.75,5.936; 52 2.25,5.936; 53 1.75,5.936; 54 1.25,5.936; 55 0.75,5.936; 56 0.25,5.936; 57 -0.25,5.936; 58 -0.75,5.936; 59 -1.25,5.936; 60 -1.75,5.936; 61 -2.25,5.936; 62 -2.75,5.936; 63 -3.25,5.936; 64 -3.75,5.936
DBZ_R-PDSO-G3 = smd 0.7 x 1: 1 -0.95,-1.1; 2 0.95,-1.1; 3 0,1.1
SOT223 = smd 1.499 x 2.007: 1 -2.261,-3.15; 2 0.025,-3.15; 3 2.311,-3.15 | smd 3.81 x 2.007: 4 0,3.15
SSOP28 = smd 0.381 x 1.905: 1 -4.55,-3.752; 2 -3.9,-3.752; 3 -3.25,-3.752; 4 -2.6,-3.752; 5 -1.95,-3.752; 6 -1.3,-3.752; 7 -0.65,-3.752; 8 0,-3.752; 9 0.65,-3.752; 10 1.3,-3.752; 11 1.95,-3.752; 12 2.6,-3.752; 13 3.25,-3.752; 14 3.9,-3.752; 15 3.9,3.752; 16 3.25,3.752; 17 2.6,3.752; 18 1.95,3.752; 19 1.3,3.752; 20 0.65,3.752; 21 0,3.752; 22 -0.65,3.752; 23 -1.3,3.752; 24 -1.95,3.752; 25 -2.6,3.752; 26 -3.25,3.752; 27 -3.9,3.752; 28 -4.55,3.752
WQP_PJ_301M6 = drill 1.016 pad 1.778 octagon: P1 0,-5.715; P2 0,-3.175; P3 0,4.445 | hole 2.2: 0,0
1X06 = drill 1.016 pad 1.88 round: 1 0,0; 2 2.54,0; 3 5.08,0; 4 7.62,0; 5 10.16,0; 6 12.7,0
2X5-1.27 = drill 0.61 pad 1.067 octagon: 1 -1.27,3.81; 2 0,3.81; 3 -1.27,2.54; 4 0,2.54; 5 -1.27,1.27; 6 0,1.27; 7 -1.27,0; 8 0,0; 9 -1.27,-1.27; 10 0,-1.27
AVR_ICSP = drill 1.016 pad 1.88 octagon: 1 -1.27,5.08; 2 1.27,5.08; 3 -1.27,2.54; 4 1.27,2.54; 5 -1.27,0; 6 1.27,0; 7 -1.27,-2.54; 8 1.27,-2.54; 9 -1.27,-5.08; 10 1.27,-5.08
LED-BICOLOR-THROUGHHOLE-5MM = drill 0.813 pad 1.676 octagon: 1 0,2.54; 2 0,0; 3 0,-2.54
SOT23-BEC = smd 1 x 1.4: B -0.95,-1.1; C 0,1.1; E 0.95,-1.1
HC49UP = smd 5.334 x 1.93: 1 -4.826,0; 2 4.826,0
R0603 = smd 1 x 1.1: 1 -0.85,0; 2 0.85,0
R1206 = smd 1.6 x 1.803: 1 -1.422,0; 2 1.422,0
ALPS_POT_VERTICAL_PS = drill 1 pad 1.88 square: P$1 -2.5,7; P$2 0,7; P$3 2.5,7 | drill 1.5 pad 2.54 octagon: P$4 -4.7,0; P$5 4.7,0
BOURNS_PTV112 = drill 1 pad 1.6 octagon: 1 -3,-11; 1P -1,-11; 2 -5,-11; 2P 1,-11; 3 5,-11; 3P 3,-11 | drill 2.8 pad 3.81 octagon: P$1 5.8,0; P$5 -5.8,0
LP4OA1PBCT = drill 0.7 octagon: L1 5,0; L2 -5,0 | drill 0.9 round: P1 2.5,2.5; P2 0,2.5; P3 -2.5,2.5; P4 2.5,-2.5; P5 0,-2.5; P6 -2.5,-2.5
TACTILE-PTH = drill 1.016 pad 1.88 round: 1 -3.251,2.261; 2 3.251,2.261; 3 -3.251,-2.261; 4 3.251,-2.261
EVQ-Q2 = smd 3.2 x 1.2: A -3.4,-2; A' 3.4,-2; B -3.4,2; B' 3.4,2

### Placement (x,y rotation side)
C1  15.56,88.9 90 top
C2  22.54,88.9 90 top
C3  53.82,86.36 0 top
C4  36.83,86.04 90 top
C5  40.96,84.14 90 top
C6  54.29,76.83 180 top
C7  58.74,76.83 0 top
C8  57.79,73.03 135 top
C9  21.91,71.12 270 top
C10  29.84,70.48 180 top
C11  36.2,70.48 0 top
C12  49.85,70.48 45 top
C13  5.71,67.94 90 top
C14  50.8,69.53 45 top
C15  21.27,66.99 270 top
C16  8.26,61.91 90 top
C17  49.53,62.87 90 top
C18  66.61,62.55 315 top
C19  65.72,60.64 315 top
C20  29.84,60.33 180 top
C21  36.2,60.33 0 top
C22  23.5,59.69 270 top
C23  32.38,58.74 270 top
C24  53.66,57.15 135 top
C25  56.2,56.07 225 top
C26  41.27,55.88 180 top
C27  44.13,51.75 180 top
C28  68.58,49.21 180 top
C29  67.63,46.67 0 top
C30  63.18,47.31 180 top
C31  84.77,43.18 90 top
C32  59.37,39.05 270 top
C33  58.74,33.34 0 top
C34  72.07,36.51 270 top
C35  75.25,35.56 90 top
C36  80.01,35.56 90 top
C37  84.77,35.56 90 top
C38  10.79,35.24 180 top
C39  47.94,34.92 180 top
C40  40.64,33.66 180 top
C41  63.82,30.8 0 top
C42  51.75,33.02 90 top
C43  81.6,30.48 270 top
C44  86.36,30.48 270 top
C45  10.79,28.26 180 top
C46  44.45,27.94 180 top
C47  72.23,60.64 180 top
C48  80.17,60.64 0 top
C49  56.52,38.1 90 top
C50  63.18,48.58 180 top
D1  11.11,87.95 270 top
D2  7.94,74.3 0 top
F1  3.17,102.87 0 top
F2  85.72,102.87 0 top
F3  2.54,2.54 0 top
F4  86.36,2.54 0 top
IC1  46.83,89.22 180 top
IC2  29.84,85.41 180 top
IC3  24.77,65.41 0 top
IC4  33.02,65.41 0 top
IC5  57.78,64.45 315 top
IC6  7.3,58.42 180 top
IC7  44.77,43.18 0 top
IC8  66.04,40.64 270 top
IC9  10.79,31.75 270 top
IC10  46.35,31.43 270 top
J1  7.62,20.95 90 top
J2  22.23,20.95 90 top
J3  36.83,20.95 90 top
J4  51.44,20.95 90 top
J5  66.04,20.95 90 top
J6  80.64,20.95 90 top
J7  7.62,6.35 90 top
J8  22.23,6.35 90 top
J9  36.83,6.35 90 top
J10  51.44,6.35 90 top
J11  66.04,6.35 90 top
J12  80.64,6.35 90 top
JP1  85.72,60.96 270 bottom
JP2  85.09,66.36 0 bottom
JP3  6.35,84.77 180 bottom
LED1  28.1,97.79 180 top
LED2  38.73,97.79 180 top
LED3  49.37,97.79 180 top
LED4  60.01,97.79 180 top
Q1  72.39,90.81 270 top
Q2  72.39,87.31 270 top
Q3  56.52,80.33 0 top
Q4  76.2,57.15 0 top
R1  16.83,97.79 270 top
R2  18.41,97.79 270 top
R3  23.97,97.79 90 top
R4  32.54,97.79 270 top
R5  34.29,97.79 270 top
R6  43.18,97.79 270 top
R7  44.93,97.79 270 top
R8  53.82,97.79 270 top
R9  55.56,97.79 270 top
R10  64.45,97.79 270 top
R11  19.05,93.98 0 top
R12  68.58,91.76 0 top
R13  80.01,91.44 90 top
R14  76.2,90.81 0 top
R15  68.58,88.27 0 top
R16  76.2,87.31 0 top
R17  80.01,80.01 90 top
R18  16.51,76.83 180 top
R19  44.13,76.83 180 top
R20  71.75,76.83 180 top
R21  29.84,75.25 180 top
R22  29.84,73.66 180 top
R23  36.2,73.66 0 top
R24  33.66,73.03 90 top
R25  29.84,72.07 0 top
R26  36.2,72.07 180 top
R27  23.5,71.12 90 top
R28  25.4,71.12 90 top
R29  26.99,71.12 90 top
R30  6.67,61.91 270 top
R31  21.91,59.69 90 top
R32  25.08,59.69 270 top
R33  26.67,59.69 270 top
R34  29.84,58.74 0 top
R35  36.2,58.74 180 top
R36  29.84,57.15 180 top
R37  36.2,57.15 0 top
R38  29.84,55.56 180 top
R39  36.2,55.56 0 top
R40  66.67,53.02 270 top
R41  64.14,53.02 270 top
R42  10.79,48.9 0 top
R43  33.02,48.9 180 top
R44  55.24,48.9 180 top
R45  77.47,48.9 180 top
R46  5.71,33.02 270 top
R47  15.88,33.02 270 top
R48  53.66,33.02 270 top
R49  40.64,32.07 0 top
R50  55.56,30.8 90 top
R51  40.64,30.48 180 top
R52  52.7,30.48 0 top
R53  78.42,30.48 270 top
R54  80.01,30.48 90 top
R55  83.19,30.48 270 top
R56  84.77,30.48 90 top
R57  5.71,29.84 270 top
R58  15.88,29.84 270 top
R59  40.64,28.89 180 top
R61  62.55,12.06 0 top
R62  75.88,12.06 180 top
SW1  7.62,97.79 0 top
SW2  72.39,97.79 0 top
SW3  81.92,97.79 0 top
SW4  84.14,88.9 270 top
SW5  84.14,77.47 270 top
U$2  [ROHS_BIG]  39.69,26.04 0 bottom

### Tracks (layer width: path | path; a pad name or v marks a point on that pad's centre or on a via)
+3V3  (via drill 0.6)
  Top 0.254: IC5.19 51.04,61.59 50.48,61.59 50.06,62.02 C17.1 48.05,62.02 v47.94,61.91 | R17.2 80.01,82.55 80.64,83.19 85.41,83.19 86.14,83.92 86.04,84.01 86.04,85.59 | IC5.32 56.26,57.53 56.8,56.99 C25.1 57.47,57.34 57.47,57.78 v62.23,62.55 | IC5.64 59.33,71.48 C8.1 58.45,72.42 59.05,73.03 v60.33,73.03 | IC1.16 51.38,86.04 | 86.04,85.59 SW4.B' | 86.04,85.59 86.04,92.39 SW4.B 86.14,94.39 86.68,94.93 86.68,96.2 86.04,96.84 77.79,96.84 77.15,96.2 77.15,94.3 76.83,93.98 76.83,93.66 | IC5.48 65.8,62.94 C18.1 66.68,63.82 69.53,63.82 | v69.53,63.5 69.53,63.82 | 76.83,93.66 76.83,93.03 77.15,92.71 77.15,90.91 R14.2 R16.2 | v65.09,81.92 65.09,87.95 64.45,88.58 64.45,93.34 v64.14,93.66 | v70.17,93.66 76.83,93.66 | 69.53,63.82 84.45,63.82 85.09,63.18 v86.36,63.18 | C29.1 66.67,46.57 66.67,45.72 67.86,44.54 IC8.27 | v66.67,50.8 R40.2 | R41.2 v64.14,50.16 64.14,48.68 C50.1 C30.1 64.14,47.2 64.14,46.04 63.29,45.19 IC8.1
  Top 0.305: 52.86,86.46 C3.1 | 52.86,86.46 52.86,87.63 51.91,88.58 v51.28,88.58 | 52.86,86.46 52.55,86.14 IC1.16 | v48.74,88.58 44.45,88.58 43.66,87.79 IC1.10 | v66.67,50.8 66.67,50.16 67.28,49.56 C28.+ 67.28,48.23 66.78,47.73 C29.1
  Top 0.406: v60.33,73.03 61.28,73.03 64.14,75.88 64.14,78.42 65.09,79.38 v65.09,81.92 44.45,81.92 43.08,83.29 | IC2.3 29.84,86.68 31.61,88.44 C4.+ 37.92,88.44 38.73,87.63 38.73,83.82 39.37,83.19 40.85,83.19 C5.1 43.08,83.29 | 43.08,83.29 43.66,83.87 IC1.10
  Bottom 0.254: v48.74,88.58 v51.28,88.58 | v64.14,50.16 64.77,50.8 v66.67,50.8 | v62.23,62.55 63.18,63.5 v69.53,63.5 | v64.14,93.66 v70.17,93.66 | v86.36,63.18 87.63,64.45 87.63,69.22 86.68,70.17 JP2.1
  Bottom 0.406: v60.33,73.03 48.9,61.59 48.26,61.59 v47.94,61.91 | v65.09,81.92 65.09,71.12 69.53,66.67 v69.53,63.5 69.53,53.66 v66.67,50.8
+3V3_A  (via drill 0.6)
  Top 0.254: 64.14,40.64 IC8.8 60.64,40.64 60.01,40.01 59.48,40.01 C32.1 | IC8.14 63.73,36.74 64.14,37.15 64.14,40.64 | 64.14,40.64 64.77,41.27 v66.36,41.27 | IC5.13 50.2,68.86 C14.1 C12.1 49.2,69.83 R19.P$1 | v82.87,71.12 81.28,71.12 80,69.83 R20.P$1 | v83.19,55.24 83.19,50.8 84.14,49.85 84.14,46.99 84.77,46.35 C31.+ | R45.P$1 80.01,41.94 80.01,43.18 80.96,44.13 84.77,44.13 C31.+ | v76.83,44.77 76.85,44.78 C31.+
  Top 0.406: IC7.2 44.77,40.06 44.77,41.91 41.91,44.77 41.91,51.58 C27.+ 41.91,51.93 41.91,54.61 42.12,54.83 C26.1 | v19.68,59.69 19.68,66.99 20.54,67.84 C15.1 21.43,68 IC3.8 | v33.66,59.69 32.49,59.69 C23.1 32.38,60.33 33.02,60.96 IC4.4 | v42.86,59.69 42.86,57.78 42.12,57.05 C26.1 | C26.1 46.04,55.88 48.58,53.34 48.58,42.55 51.72,39.4 C49.+ 56.55,39.37 57.47,39.37 58,39.9 | 58,39.9 C32.1 | R44.P$1 57.78,41.85 57.78,40.64 58,40.42 58,39.9
  Bottom 0.254: v66.36,41.27 70.48,41.27 73.98,44.77 v76.83,44.77 | v83.19,55.24 83.19,70.8 v82.87,71.12
  Bottom 0.406: v19.68,59.69 v33.66,59.69 v42.86,59.69 46.63,63.46 R19.P$1
AREF_-10  (via drill 0.6)
  Top 0.254: 8.47,61.28 C16.1 8.36,60.96 10.48,60.96 | v27.62,73.66 R22.2 | 27.62,77.15 v27.62,77.79 | 27.62,77.15 34.29,77.15 37.05,74.4 R23.2 | 13.97,74.3 12.7,74.3 10.48,72.07 10.48,60.96 | 13.97,74.3 16.19,74.3 20.64,78.74 21.91,78.74 23.5,77.15 27.62,77.15 | v27.3,39.37 30.48,39.37 | 30.48,39.37 v36.2,39.37 37.15,40.32 37.15,44.77 27.94,53.98 27.94,56.52 28.57,57.15 R36.2 | R43.P$3 30.48,41.85 30.48,39.37 | R37.2 38.1,57.15 38.42,56.83 38.42,51.12 39.69,49.85 39.69,47.94 39.05,47.31 39.05,39.69 v39.37,39.37 | 13.97,74.3 v13.97,75.25 | 10.48,60.96 22.54,48.9 22.54,40.01 v21.91,39.37
  Top 0.406: C16.1 R30.2 6.67,60.33 6.35,60.01 IC6.2
  Bottom 0.254: v27.62,77.79 v27.62,73.66 | v21.91,39.37 v27.3,39.37 | v36.2,39.37 v39.37,39.37 | R18.P$3 13.97,69.88 v13.97,75.25
BLEND_CV
  Top 0.254: IC5.21 51.18,60.33 46.99,60.33 43.5,63.82 37.15,63.82 36.83,63.5 IC4.7 36.83,61.28 37.05,61.06 C21.2 R35.1
BLEND_POT  (via drill 0.6)
  Top 0.254: IC5.23 50.8,58.53 50.8,52.39 53.98,49.21 53.98,47.31 56.52,44.77 v56.52,44.13
  Bottom 0.254: v56.52,44.13 56.83,43.81 58.74,43.81 61.91,40.64 63.5,40.64 64.45,39.69 75.88,39.69 77.47,41.27 R45.P$2
BOOT_FLASH  (via drill 0.6)
  Top 0.254: R13.2 SW4.A SW4.A' 80.74,85.5 80.01,84.77 75.56,84.77 74.61,83.82 v74.61,83.19 | IC5.60 65.79,74.93 67.63,74.93 69.22,76.52 69.22,82.87 v68.9,83.19
  Bottom 0.254: v68.9,83.19 v74.61,83.19
DENSITY_CV
  Top 0.254: C22.2 R31.1 21.17,58.84 20.95,59.05 20.95,61.91 21.91,62.87 22.8,62.87 IC3.1 22.86,64.14 23.81,65.09 44.45,65.09 45.09,65.72 50.16,65.72 50.95,64.93 IC5.17
GND  (via drill 0.6)
  other vias: 10.79,30.48 86.36,26.67 57.15,29.84 41.12,92.39 33.02,70.8 27.94,67.94 27.94,62.55 32.38,56.2 47.94,64.45 73.34,34.29 52.07,54.29 68.42,62.55 58.42,74.61 15.56,83.5 45.72,26.04 46.99,36.51 20.95,64.77 46.99,48.9 61.59,50.8 70.8,52.39 67.63,56.2 71.44,46.35 72.39,41.27 49.21,72.07 56.52,78.74 1.27,104.78 8.89,104.78 16.51,104.78 24.13,104.78 31.75,104.78 39.37,104.78 46.99,104.78 54.61,104.78 62.23,104.78 69.85,104.78 77.47,104.78 85.09,104.78 87.63,102.87 87.63,95.25 87.63,41.91 87.63,3.81 87.63,11.43 85.09,1.27 77.47,1.27 69.85,1.27 62.23,1.27 54.61,1.27 46.99,1.27 31.75,1.27 16.51,1.27 1.27,1.27 1.27,8.89 1.27,16.51 87.63,80.01 87.63,73.03 40.64,58.1 40.64,60.64 27.62,57.47 65.09,42.55 67.63,38.42 73.03,59.05 76.2,65.41 79.38,59.05 67.94,86.68 69.85,85.09 58.74,69.22 45.4,60.01 45.4,64.45 53.02,64.14 42.23,42.86 47.31,42.86 33.66,92.08 36.83,80.96 40.96,87.63 7.62,68.58 8.89,56.52 56.36,86.36 22.54,83.5 59.37,36.51
  pour Bottom: 0,106.05 0,0 88.9,0 88.9,106.05
  pour Top: 0,106.05 88.9,106.05 88.9,0 0,0
I2C_SCL  (via drill 0.6)
  Top 0.254: IC5.29 59.05,62.54 v59.05,63.18 | 69.84,42.55 IC8.24 68.53,42.59 65.72,45.4 65.72,53.98 | 65.72,53.98 65.72,55.56 v66.04,55.88 | R40.1 66.57,53.98 65.72,53.98
  Bottom 0.254: v66.04,55.88 66.04,56.2 v59.05,63.18
I2C_SDA  (via drill 0.6)
  Top 0.254: IC5.30 58.82,61.59 v59.37,61.59 | IC8.23 69.76,41.91 68.26,41.91 65.09,45.09 65.09,53.98 | 65.09,53.98 65.09,54.93 v64.77,55.24 | R41.1 64.24,53.98 65.09,53.98
  Bottom 0.254: v59.37,61.59 59.69,61.59 64.77,56.52 v64.77,55.24
I2S_LRCK
  Top 0.254: 62.24,42.55 IC8.5 63.45,42.59 63.82,42.23 63.82,41.59 63.5,41.27 62.3,41.27 IC8.7 60.95,41.29 55.56,46.67 55.56,51.44 59.05,54.93 59.05,57.15 59.3,57.39 IC5.33
I2S_SCK  (via drill 0.6)
  Top 0.254: IC8.3 61.2,43.89 57.47,47.62 57.47,50.48 60.64,53.66 v60.96,53.66 | v60.01,56.2 60.33,56.52 60.33,57.32 IC5.34
  Bottom 0.254: v60.96,53.66 60.01,54.61 v60.01,56.2
I2S_SIN
  Top 0.254: 62.32,41.91 IC8.6 61.25,41.94 56.2,46.99 56.2,51.12 60.92,55.84 60.92,57.43 IC5.35
I2S_SOUT
  Top 0.254: 62.35,43.18 IC8.4 60.9,43.24 56.83,47.31 56.83,50.8 61.59,55.56 61.59,57.46 IC5.36
JTCK
  Top 0.254: IC5.49 64.99,66.36 70.17,66.36 71.44,67.63 82.87,67.63 84.14,68.9 JP2.4
JTDI  (via drill 0.6)
  Top 0.254: IC5.50 64.92,66.99 69.85,66.99 71.12,68.26 78.74,68.26 v79.06,68.58 | JP2.8 80.01,66.36 v79.06,65.41
  Bottom 0.254: v79.06,68.58 v79.06,65.41
JTDO
  Top 0.254: IC5.55 61.91,67.52 61.91,66.67 63.5,65.09 64.45,65.09 65.09,65.72 70.48,65.72 71.75,66.99 83.19,66.99 83.82,67.63 JP2.6
JTMS  (via drill 0.6)
  Top 0.254: IC5.46 63.18,62.94 63.18,63.5 63.5,63.82 64.77,63.82 65.41,64.45 80.01,64.45 v80.96,65.41 | v80.96,68.58 82.87,68.58 84.45,70.17 JP2.2
  Bottom 0.254: v80.96,65.41 v80.96,68.58
LED_DATA  (via drill 0.6)
  Top 0.254: IC1.14 48.74,84.77 49.05,84.45 60.64,84.45 v61.59,85.41 | 60.33,67.63 v60.01,67.63 60.61,67.63 IC5.57
  Bottom 0.254: v61.59,85.41 61.59,82.23 62.23,81.6 62.23,69.53 60.33,67.63 v60.01,67.63
LED_EN  (via drill 0.6)
  Top 0.254: IC1.12 46.2,84.77 47.15,83.82 61.91,83.82 v62.55,84.45 | IC5.24 54.29,61.31 v54.29,61.91
  Bottom 0.254: v62.55,84.45 62.55,82.23 62.87,81.92 62.87,69.22 60.33,66.67 59.69,66.67 59.05,67.31 56.52,67.31 54.29,65.09 v54.29,61.91
LED_REC
  Top 0.254: IC5.62 64.77,75.33 64.77,78.11 66.04,79.38 66.04,88.58 65.41,89.22 65.41,93.03 65.72,93.34 65.72,99.38 63.5,101.6 19.68,101.6 18.41,100.33 R2.1 R1.1
LED_SCK  (via drill 0.6)
  Top 0.254: IC1.11 | IC1.11 44.93,84.77 46.51,83.19 63.18,83.19 v63.5,83.5 | IC5.25 55.24,61.56 v55.24,63.18
  Bottom 0.254: v63.5,83.5 63.5,68.9 60.64,66.04 59.37,66.04 58.74,66.67 56.83,66.67 55.24,65.09 v55.24,63.18
LIN
  Top 0.254: C37.+ 84.77,38.42 83.2,39.99 IC8.20
LOUT
  Top 0.254: C33.+ 60.33,33.35 60.33,37.78 60.58,38.04 IC8.12
LOUT_JACK
  Top 0.254: R61.1 61.59,11.96 J11.P3
N$1  (via drill 0.6)
  Top 0.254: R21.2 27.62,75.25 26.67,74.3 20.32,74.3 19.05,73.03 13.34,73.03 11.75,71.44 11.75,61.59 23.81,49.53 23.81,32.07 29.84,26.04 v30.48,26.04 | v33.02,18.41 45.4,18.41 46.99,20 J4.P3
  Bottom 0.254: v30.48,26.04 30.48,19.68 31.75,18.41 v33.02,18.41
N$2
  Top 0.254: IC4.13 30.48,69.53 30.7,69.75 C10.1 R25.2 R22.1 R21.1
N$4
  Top 0.254: R24.2 33.66,75.56 32.7,76.52 23.81,76.52 22.23,74.93 20,74.93 18.73,73.66 13.02,73.66 11.11,71.75 11.11,61.28 23.18,49.21 23.18,31.75 30.8,24.13 30.8,19.37 32.7,17.46 45.72,17.46 46.99,16.19 J10.P3
N$5
  Top 0.254: R26.2 R23.1 | R26.2 C11.1 35.34,69.75 35.56,69.53 IC4.9 | R26.2 35.24,72.17 R24.1
N$6
  Top 0.254: R39.2 36.83,55.35 36.83,50.8 35.88,49.85 35.88,47.94 38.42,45.4 38.42,37.47 34.29,33.34 34.29,26.04 36.2,24.13 74.61,24.13 76.2,22.54 J6.P3
N$7
  Top 0.254: IC5.5 54.29,70.42 54.29,72.71 57.15,75.56 59.05,75.56 59.59,76.1 C7.2 59.69,76.94 59.69,80.01 60.01,80.33 Q3.2
N$8
  Top 0.254: IC5.6 53.66,70.35 53.66,74.93 53.44,75.14 C6.2 53.34,76.94 53.34,79.38 52.39,80.33 Q3.1
N$9
  Top 0.254: LED4.3 58.32,98.64 R9.1
N$10
  Top 0.254: R38.2 29,53.87 37.78,45.09 37.78,37.78 33.66,33.66 33.66,25.72 35.88,23.5 59.69,23.5 61.59,21.59 J5.P3
N$11
  Top 0.254: IC4.2 30.48,61.28 30.7,61.06 C20.1 R34.2 R36.1 R38.1
N$12
  Top 0.254: LED4.1 63.4,98.64 R10.1
N$13
  Top 0.254: IC5.47 65.05,61.78 C19.1
N$14
  Top 0.254: R32.2 25.08,32.7 30.16,27.62 31.43,27.62 32.38,26.67 32.38,22.86 33.66,21.59 33.66,19.68 34.29,19.05 43.81,19.05 45.09,20.32 45.09,21.27 46.35,22.54 47.62,22.54 48.9,21.27 48.9,5.71 47.62,4.45 33.02,4.45 32.38,5.08 J9.P3
N$15
  Top 0.254: R39.1 R37.1 R35.2 C21.1 35.34,61.06 35.56,61.28 IC4.6
N$16
  Top 0.254: LED3.1 52.76,98.64 R8.1
N$17
  Top 0.254: IC8.16 69.82,37.36 C34.1 75.05,37.36 C35.+
N$18
  Top 0.254: R55.1 R56.2 | R56.2 C44.1 | R56.2 C37.-
N$19
  Top 0.254: IC5.31 54.41,56.48 C24.1
N$20
  Top 0.254: R58.2 15.88,8.89 17.78,6.99 J8.P3
N$21
  Top 0.254: 15.24,3.17 23.5,3.17 25.4,5.08 J8.P2 | R57.2 5.71,24.45 6.67,23.5 13.97,23.5 15.24,22.23 15.24,3.17 | 15.24,3.17 5.08,3.17 3.17,5.08 J7.P3
N$22
  Top 0.254: R53.1 R54.2 | R54.2 C43.1 | R54.2 C36.-
N$23
  Top 0.254: R52.2 53.98,30.48 55.14,31.65 R50.2 | R50.2 55.66,31.75 | C41.- 57.78,30.8 56.94,31.65 R50.2
N$24
  Top 0.254: R33.1 R32.1 24.13,60.54 | 24.13,60.54 C22.1 R31.2 | 24.13,60.54 IC3.2
N$25
  Top 0.254: IC10.6 50.16,30.8 50.48,30.48 R52.1 51.75,30.58 C42.1 R48.2
N$26
  Top 0.254: R43.P$2 33.02,46.99 26.67,53.34 R33.2
N$27
  Top 0.254: R29.2 26.99,72.71 26.04,73.66 20.64,73.66 19.37,72.39 13.65,72.39 12.38,71.12 12.38,61.91 24.45,49.85 24.45,32.38 29.84,26.99 31.11,26.99 31.75,26.35 31.75,22.54 32.38,21.91 J3.P3
N$28
  Top 0.254: R48.1 C42.2 51.02,33.87 50.8,33.66 50.8,32.7 50.16,32.07 IC10.7 47.62,32.07 47.31,31.75 47.31,28.89 47.62,28.57 52.07,28.57 52.7,27.94 75.56,27.94 78.11,25.4 78.11,17.78 75.03,14.71 R62.2
N$29
  Top 0.254: LED3.3 47.68,98.64 R7.1
N$30
  Top 0.254: R28.1 R29.1 | IC3.6 R28.1 | R28.1 25.18,70.48 24.77,70.48 24.45,70.8 24.45,71.75 24.23,71.97 R27.2 C9.1
N$31
  Top 0.254: R59.2 R51.2 39.05,30.48 38.73,30.8 38.73,34.61 39.53,35.4 43.66,35.4 45.72,37.47 49.53,37.47 51.75,35.24 56.2,35.24 57.15,34.29 C33.-
N$32
  Top 0.254: R49.2 C40.1 | R51.1 41.59,30.48 41.49,30.58 R49.2 | R49.2 IC10.2
N$33
  Top 0.254: R49.1 C40.2 39.79,34.08 40.32,34.61 43.18,34.61 43.81,33.97 43.81,33.4 IC10.1 45.09,33.34 46.67,31.75 46.67,28.57 47.31,27.94 51.75,27.94 52.39,27.3 75.25,27.3 77.47,25.08 77.47,18.1 71.44,12.06 R61.2
N$34
  Top 0.254: LED2.1 42.12,98.64 R6.1
N$35
  Top 0.254: R18.P$2 16.51,71.44 16.83,71.75 19.68,71.75 20.95,73.03 25.08,73.03 25.4,72.71 R28.2
N$36  (via drill 0.6)
  Top 0.254: R15.1 67.73,89.11 66.67,90.17 66.67,92.39 66.99,92.71 66.99,100.33 64.45,102.87 7.94,102.87 6.35,101.28 6.35,99.38 3.49,96.52 3.49,94.3 1.91,92.71 1.91,25.08 4.45,22.54 4.45,20 6.35,18.1 v13.97,18.1
  Bottom 0.254: v13.97,18.1 16.51,18.1 17.78,19.37 J2.P3
N$37
  Top 0.254: R15.2 Q2.B
N$38
  Top 0.254: R2.2 R1.2 16.73,96.84 13.65,96.84 12.7,97.79 SW1.L1
N$39
  Top 0.254: LED2.3 37.05,98.64 R5.1
N$40
  Top 0.254: R3.1 23.97,95.89 24.61,95.25 LED1.1
N$41
  Top 0.254: LED1.3 29.79,98.64 R4.1
N$42  (via drill 0.6)
  Top 0.254: R42.2P R42.3P 17.46,34.23 v17.46,32.38 17.46,26.35 19.37,24.45 19.37,19.05 29.53,8.89 29.53,4.76 31.11,3.17 76.83,3.17 78.42,4.76 78.42,8.89 78.74,9.21 78.74,25.72 78.42,26.04 R53.2 | v11.43,32.38 IC9.7
  Bottom 0.254: v17.46,32.38 v11.43,32.38
N$43
  Top 0.254: IC1.15 50.01,89.85 50.64,90.49 52.86,90.49 56.04,93.66 62.23,93.66 64.45,95.89 R10.2
N$44
  Top 0.254: IC1.1 51.28,93.66 52.23,94.61 54.29,94.61 55.56,95.89 R9.2
N$45
  Top 0.254: IC1.2 50.01,93.66 51.59,95.25 53.18,95.25 53.82,95.89 R8.2
N$46
  Top 0.254: R7.2 44.93,96.2 45.24,95.89 46.51,95.89 48.74,93.66 IC1.3
N$47
  Top 0.254: R6.2 43.18,96.2 44.13,95.25 45.88,95.25 47.47,93.66 IC1.4
N$48
  Top 0.254: IC1.5 46.2,93.66 45.24,94.61 40.32,94.61 39.37,93.66 36.51,93.66 34.29,95.89 R5.2
N$49
  Top 0.254: IC1.6 44.93,91.12 44.29,90.49 40.64,90.49 39.37,91.76 35.88,91.76 33.66,93.98 27.62,93.98 26.99,94.61 24.45,94.61 23.02,96.04 23.02,98.42 23.23,98.64 R3.2
N$50
  Top 0.254: R4.2 32.54,96.52 36.04,93.03 39.69,93.03 40.64,93.98 43.34,93.98 43.66,93.66 IC1.7
N$51  (via drill 0.6)
  Top 0.254: IC9.1 8.26,33.72 v8.26,35.56 | R42.2 5.79,38.81 6.67,39.69 15.24,39.69 15.88,39.05 15.88,37.98 R42.3 15.79,36.91 18.1,34.61 18.1,33.34 18.41,33.02 18.41,31.75 18.1,31.43 18.1,26.67 20,24.77 20,19.37 30.16,9.21 30.16,5.08 31.43,3.81 76.52,3.81 77.79,5.08 77.79,8.89 v77.47,9.21 | R55.2 83.19,26.99 82.55,26.35 82.55,20 79.38,16.83 79.38,9.53 v79.69,9.21
  Bottom 0.254: v8.26,35.56 6.67,35.56 5.79,36.43 R42.2 | v77.47,9.21 v79.69,9.21
N$52
  Top 0.254: R42.1P 9.84,37.85 9.84,37.15 10.48,36.51 13.97,36.51 15.88,34.61 R47.1
N$53
  Top 0.254: R46.1 5.71,35.56 7.79,37.64 R42.1
N$54
  Top 0.254: R47.2 R58.1 15.03,30.7 14.61,31.11 IC9.6
N$55
  Top 0.406: R11.2 21.59,93.98 22.54,93.03 C2.+ 22.68,91.44 25.4,91.44 26.63,90.21 IC2.2
N$56  (via drill 0.6)
  Top 0.406: D1.A 11.11,86.04 v11.11,80.96 | JP3.1 JP3.2
  Bottom 0.406: JP3.2 8.89,79.69 9.84,79.69 v11.11,80.96
N$57
  Top 0.254: R12.1 67.73,92.61 67.63,92.71 67.63,100.65 64.77,103.5 6.35,103.5 1.27,98.42 1.27,24.45 3.17,22.54 J1.P3
N$58
  Top 0.254: R57.1 R46.2 5.93,32.38 IC9.2
N$59
  Top 0.254: IC8.26 71.19,43.89 75.88,48.58 75.88,51.12 71.12,55.88 71.12,56.9 Q4.1 71.22,57.3 71.38,57.46 C47.2
N$60
  Top 0.254: IC8.25 71.5,43.24 76.52,48.26 76.52,51.12 81.03,55.63 Q4.2 81.18,57.3 81.02,57.46 C48.2
N$64
  Top 0.406: JP3.9 JP3.10 8.57,89.85 9.53,88.9 9.53,78.74 6.04,75.25 D2.C
N$66
  Top 0.254: R12.2 Q1.B
PITCH_POT  (via drill 0.6)
  Top 0.254: v71.75,65.41 71.44,65.09 65.09,65.09 64.45,64.45 57.43,64.45 IC5.9
  Bottom 0.254: v71.75,65.41 R20.P$2
PLAY
  Top 0.254: R16.1 Q2.C 73.66,87.14 73.66,85.72 70.48,82.55 70.48,75.88 68.26,73.66 65.93,73.66 IC5.58
POSITION_POT_CV
  Top 0.254: C9.2 R27.1 23.5,70.17 24.13,69.53 IC3.7 24.13,66.67 25.08,65.72 44.13,65.72 44.77,66.36 50.58,66.36 IC5.16 50.89,66.04
REC
  Top 0.254: R14.1 Q1.C 73.66,90.64 73.66,88.9 73.34,88.58 72.39,88.58 72.39,85.41 69.85,82.87 69.85,76.2 67.94,74.3 65.86,74.3 IC5.59
RESET  (via drill 0.6)
  Top 0.254: 86.14,77.79 SW5.B' 86.04,73.97 86.04,72.07 87.63,70.48 87.63,64.45 87.31,64.14 85.41,64.14 85.09,64.45 JP2.10 | 86.14,77.79 SW5.B | 80.01,77.79 80.01,75.88 75.88,71.75 67.94,71.75 66.36,70.17 v66.36,67.94 | IC5.7 57.78,65.51 v57.78,65.41 | 80.01,77.79 R17.1 | 80.01,77.79 86.14,77.79
  Bottom 0.254: v66.36,67.94 63.82,65.41 61.91,65.41 61.28,64.77 58.42,64.77 v57.78,65.41
RIN
  Top 0.254: C36.+ 80.01,38.42 79.09,39.34 IC8.19
ROUT
  Top 0.254: C41.+ 65.41,30.81 65.41,32.38 62.55,35.24 61.28,35.24 60.96,35.56 60.96,37.15 61.2,37.39 IC8.13
ROUT_JACK
  Top 0.254: J12.P3 76.2,10.16 76.73,10.69 R62.1
RX
  Top 0.254: IC5.43 65.58,58.42 66.67,58.42 68.1,59.85 68.1,60.8 70.48,63.18 83.82,63.18 84.77,62.23 86.36,62.23 87,61.59 87,53.98 86.36,53.34 JP1.4
SIZE_CV
  Top 0.254: R25.1 C10.2 29,69.75 29.21,69.53 IC4.14 29.21,67.31 30.16,66.36 43.81,66.36 44.45,66.99 50.65,66.99 IC5.15
SIZE_POT
  Top 0.254: R19.P$2 44.13,71.44 46.35,73.66 50.16,73.66 53.02,70.8 53.02,69.57 IC5.8
SW_LOAD
  Top 0.254: IC5.51 65.41,68.18 65.41,70.17 67.63,72.39 68.9,72.39 71.75,75.25 71.75,81.92 75.25,85.41 78.11,85.41 78.66,85.97 SW3.3 SW3.4
SW_MODE  (via drill 0.6)
  Top 0.254: IC5.52 64.77,68.25 64.77,70.48 67.31,73.03 68.58,73.03 71.12,75.56 71.12,82.23 74.93,86.04 77.47,86.04 78.11,86.68 78.11,93.34 v77.79,93.66 | SW2.4 SW2.3
  Bottom 0.254: v77.79,93.66 75.92,95.53 SW2.4
SW_REC
  Top 0.254: SW1.P5 SW1.P2 9.56,102.23 63.82,102.23 66.36,99.69 66.36,93.03 66.04,92.71 66.04,89.53 66.67,88.9 66.67,79.06 65.41,77.79 65.41,75.25 IC5.61
TEXTURE_CV
  Top 0.254: R26.1 C11.2 37.05,69.75 36.83,69.53 IC4.8 36.83,67.31 37.15,66.99 43.5,66.99 44.13,67.63 50.72,67.63 IC5.14
TEXTURE_POT
  Top 0.254: IC5.22 50.16,58.6 50.16,52.07 53.34,48.9 53.34,46.99 55.24,45.09 R44.P$2
TX
  Top 0.254: IC5.42 65.35,57.94 66.83,57.94 68.58,59.69 68.58,60.64 70.64,62.71 81.76,62.71 84.14,60.33 84.14,51.12 84.45,50.8 JP1.5
V_OCT
  Top 0.254: R34.1 C20.2 29,61.06 29.21,61.28 IC4.1 29.21,63.5 30.16,64.45 43.81,64.45 47.31,60.96 51.11,60.96 IC5.20
VCC  (via drill 0.6)
  Top 0.406: IC9.8 13.34,33.72 13.28,33.66 12.38,33.66 11.64,34.39 C38.1 v13.34,35.24 | v2.86,33.97 3.49,34.61 3.49,41.27 7.62,45.4 v7.62,50.8 7.62,53.66 3.17,58.1 3.17,90.49 4.45,91.76 14.92,91.76 15.38,91.3 C1.+ | v9.53,50.8 9.53,51.12 11.43,49.21 11.43,44.77 20.95,35.24 20.95,31.11 29.37,22.7 29.37,18.89 32.7,15.56 41.59,15.56 41.91,15.24 v45.4,15.24 | v48.9,36.2 48.79,36.09 C39.1 48.79,33.5 IC10.8 | v48.9,39.05 47.92,40.03 IC7.3 | D1.C 13.97,89.85 15.42,91.3 C1.+ | C1.+ 15.73,91.48 | R11.1 16.51,93.98 15.56,93.03 C1.+
  Bottom 0.406: v2.86,33.97 12.06,33.97 v13.34,35.24 | v7.62,50.8 v9.53,50.8 | v45.4,15.24 45.4,22.86 48.9,26.35 v48.9,36.2 v48.9,39.05
VEE  (via drill 0.6)
  Top 0.406: IC9.4 8.2,28.95 8.89,28.26 C45.2 9.84,28.16 v9.84,26.67 | v4.13,27.94 4.13,40.96 8.57,45.4 8.57,53.66 | 5.71,62.76 5.29,62.76 4.13,61.59 4.13,58.1 8.57,53.66 | 5.71,62.76 R30.1 | 5.71,62.76 C13.- 5.86,65.41 7.62,65.41 8.89,66.67 8.89,72.39 9.84,73.34 D2.A | 8.57,53.66 12.06,50.16 12.06,45.09 21.59,35.56 21.59,31.43 30.16,22.86 30.16,19.05 33.02,16.19 v44.13,16.19 | IC10.4 43.76,28.09 C46.2 43.6,26.14 44.02,25.72 v44.13,25.72
  Bottom 0.406: v4.13,27.94 8.57,27.94 v9.84,26.67 | v44.13,16.19 v44.13,25.72

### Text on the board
tNames: SYSBOOT | RESET | Clouds | cc-by-sa Olivier Gillet, 2015. v3
bNames: Red Stripe | -12V | Clouds | GND | GND | GND | +12V | JTAG | GND | <TX | FTDI DONGLE | cc-by-sa Olivier Gillet, 2015. v3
